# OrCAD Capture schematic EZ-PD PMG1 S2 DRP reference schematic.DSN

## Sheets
1 02. PMG1-S2 CONTROLLER: size A3; title: PMG1-S2 DRP REFERENCE DESIGN; rev: 01; note: 630-XXXXX-XX
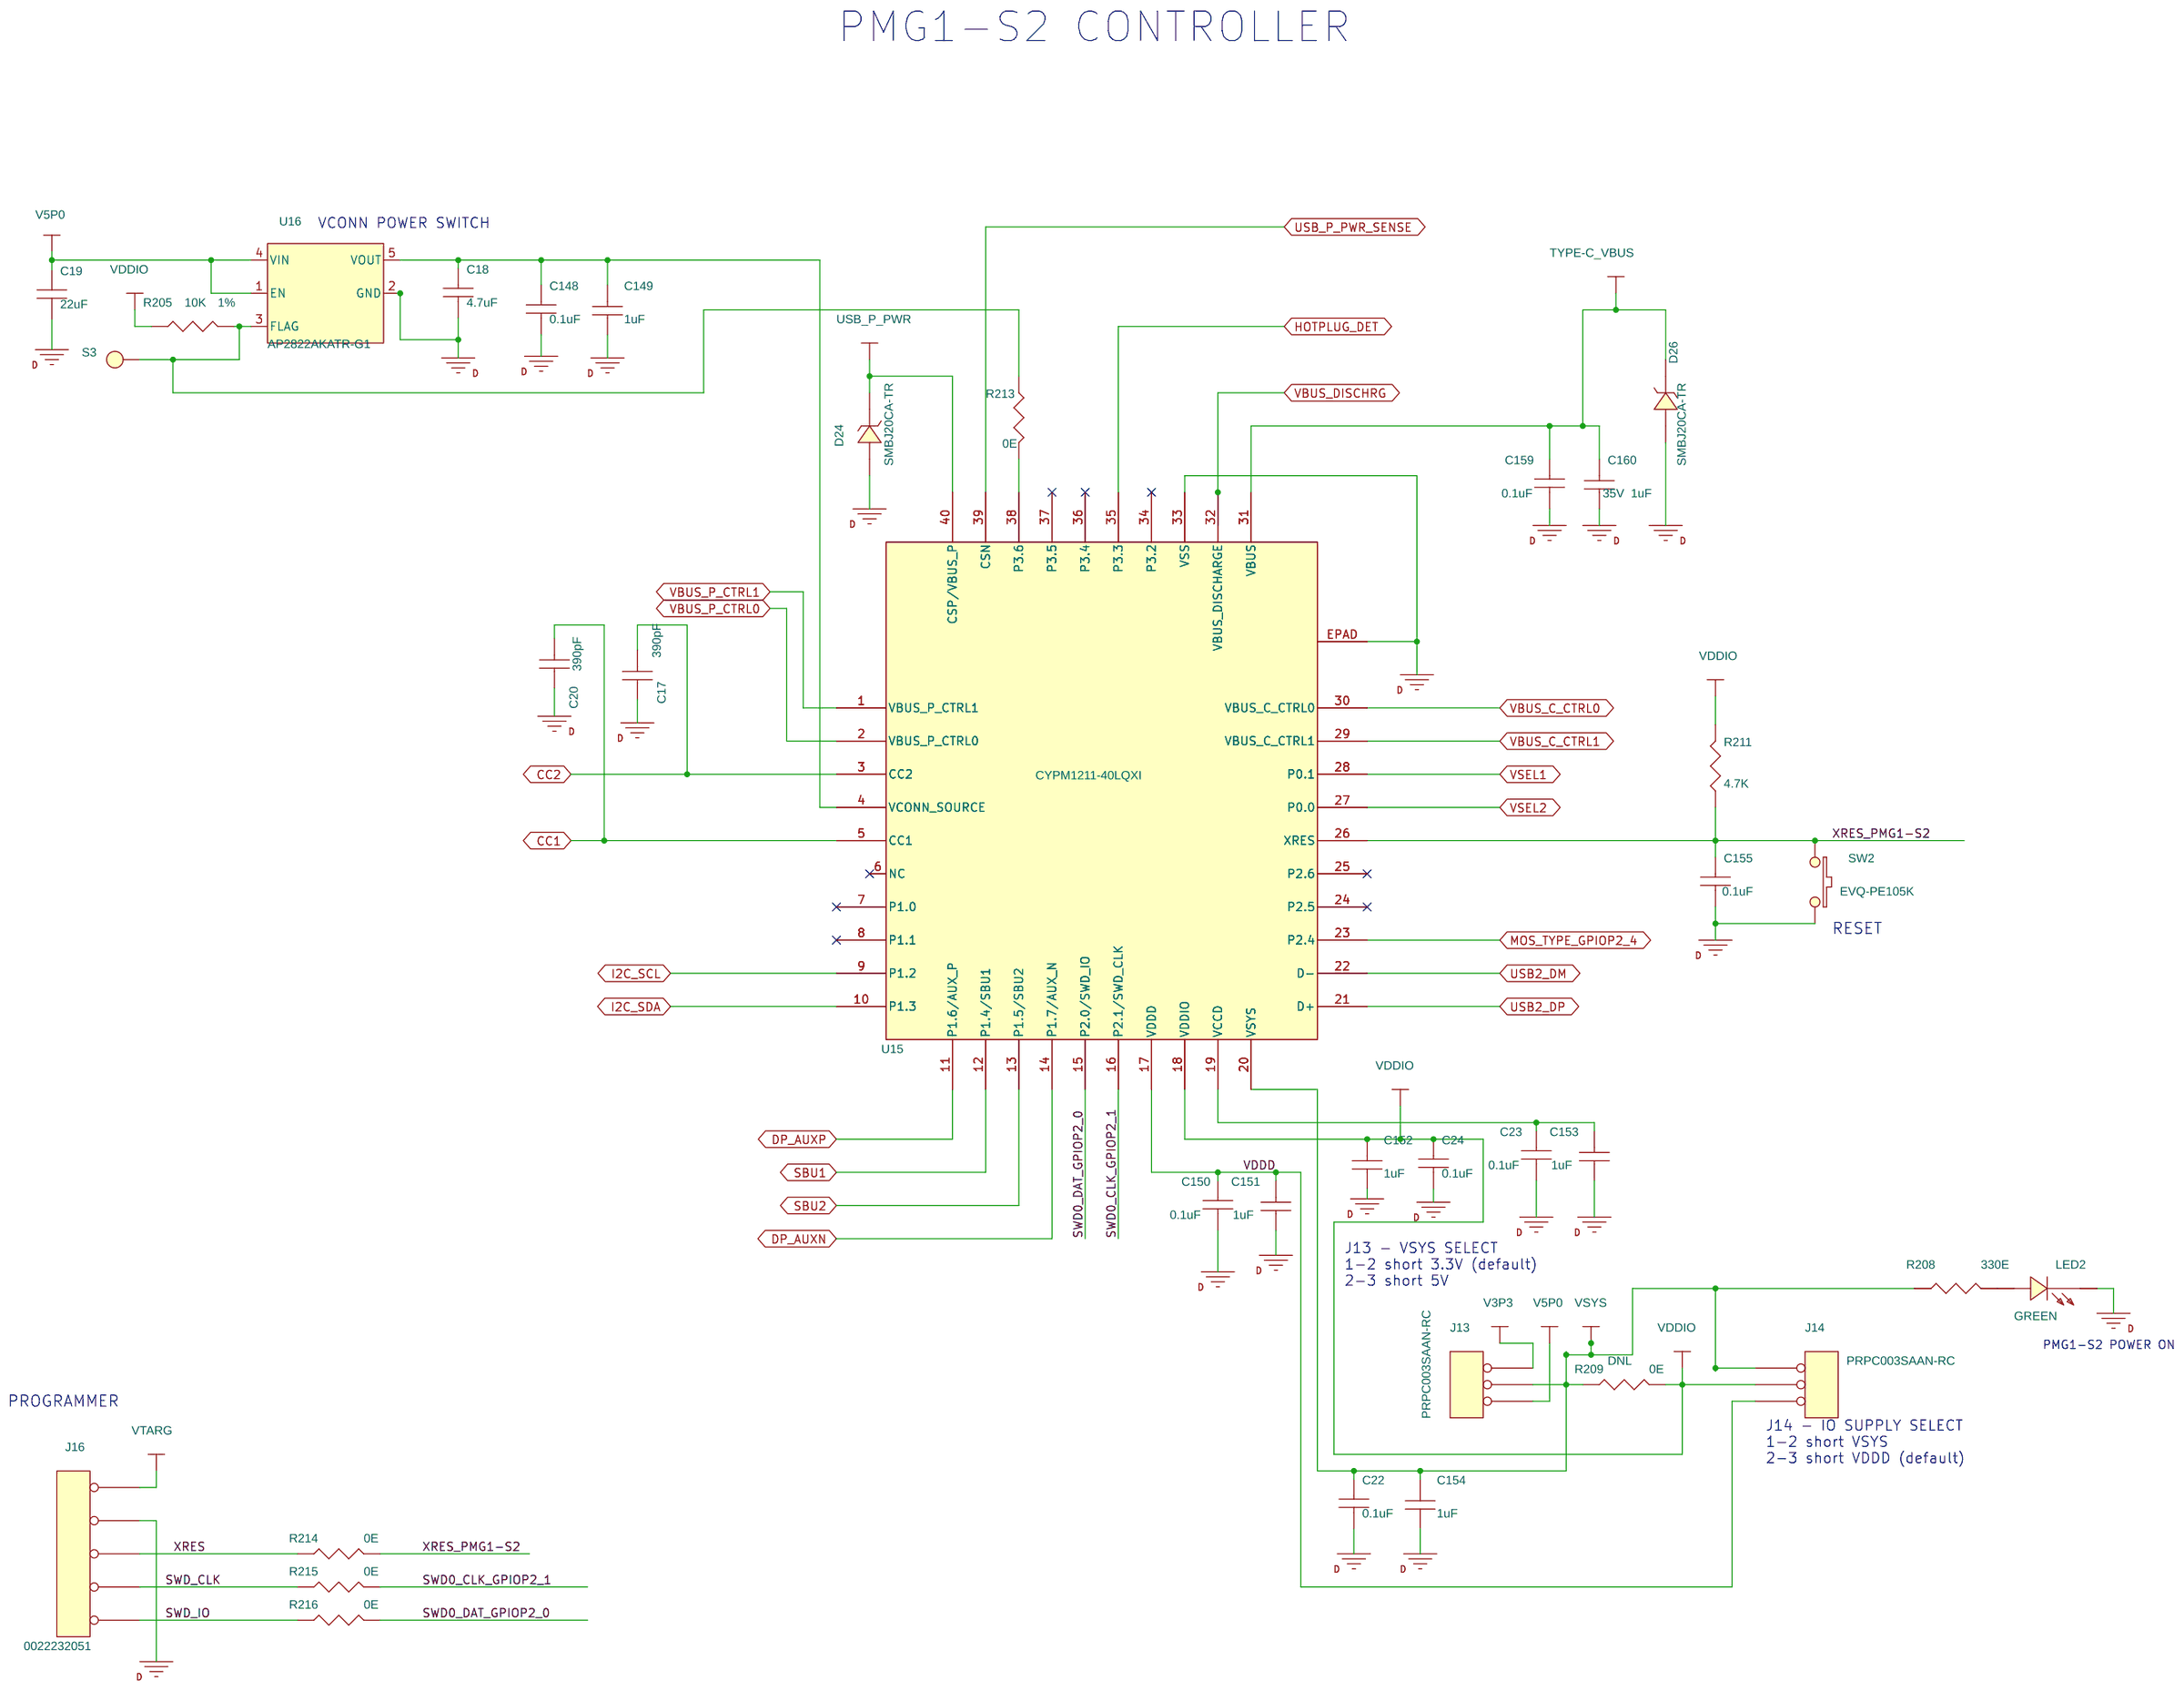
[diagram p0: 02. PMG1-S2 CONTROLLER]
2 06. USB SUPERSPEED AND DISPLAY: size A3
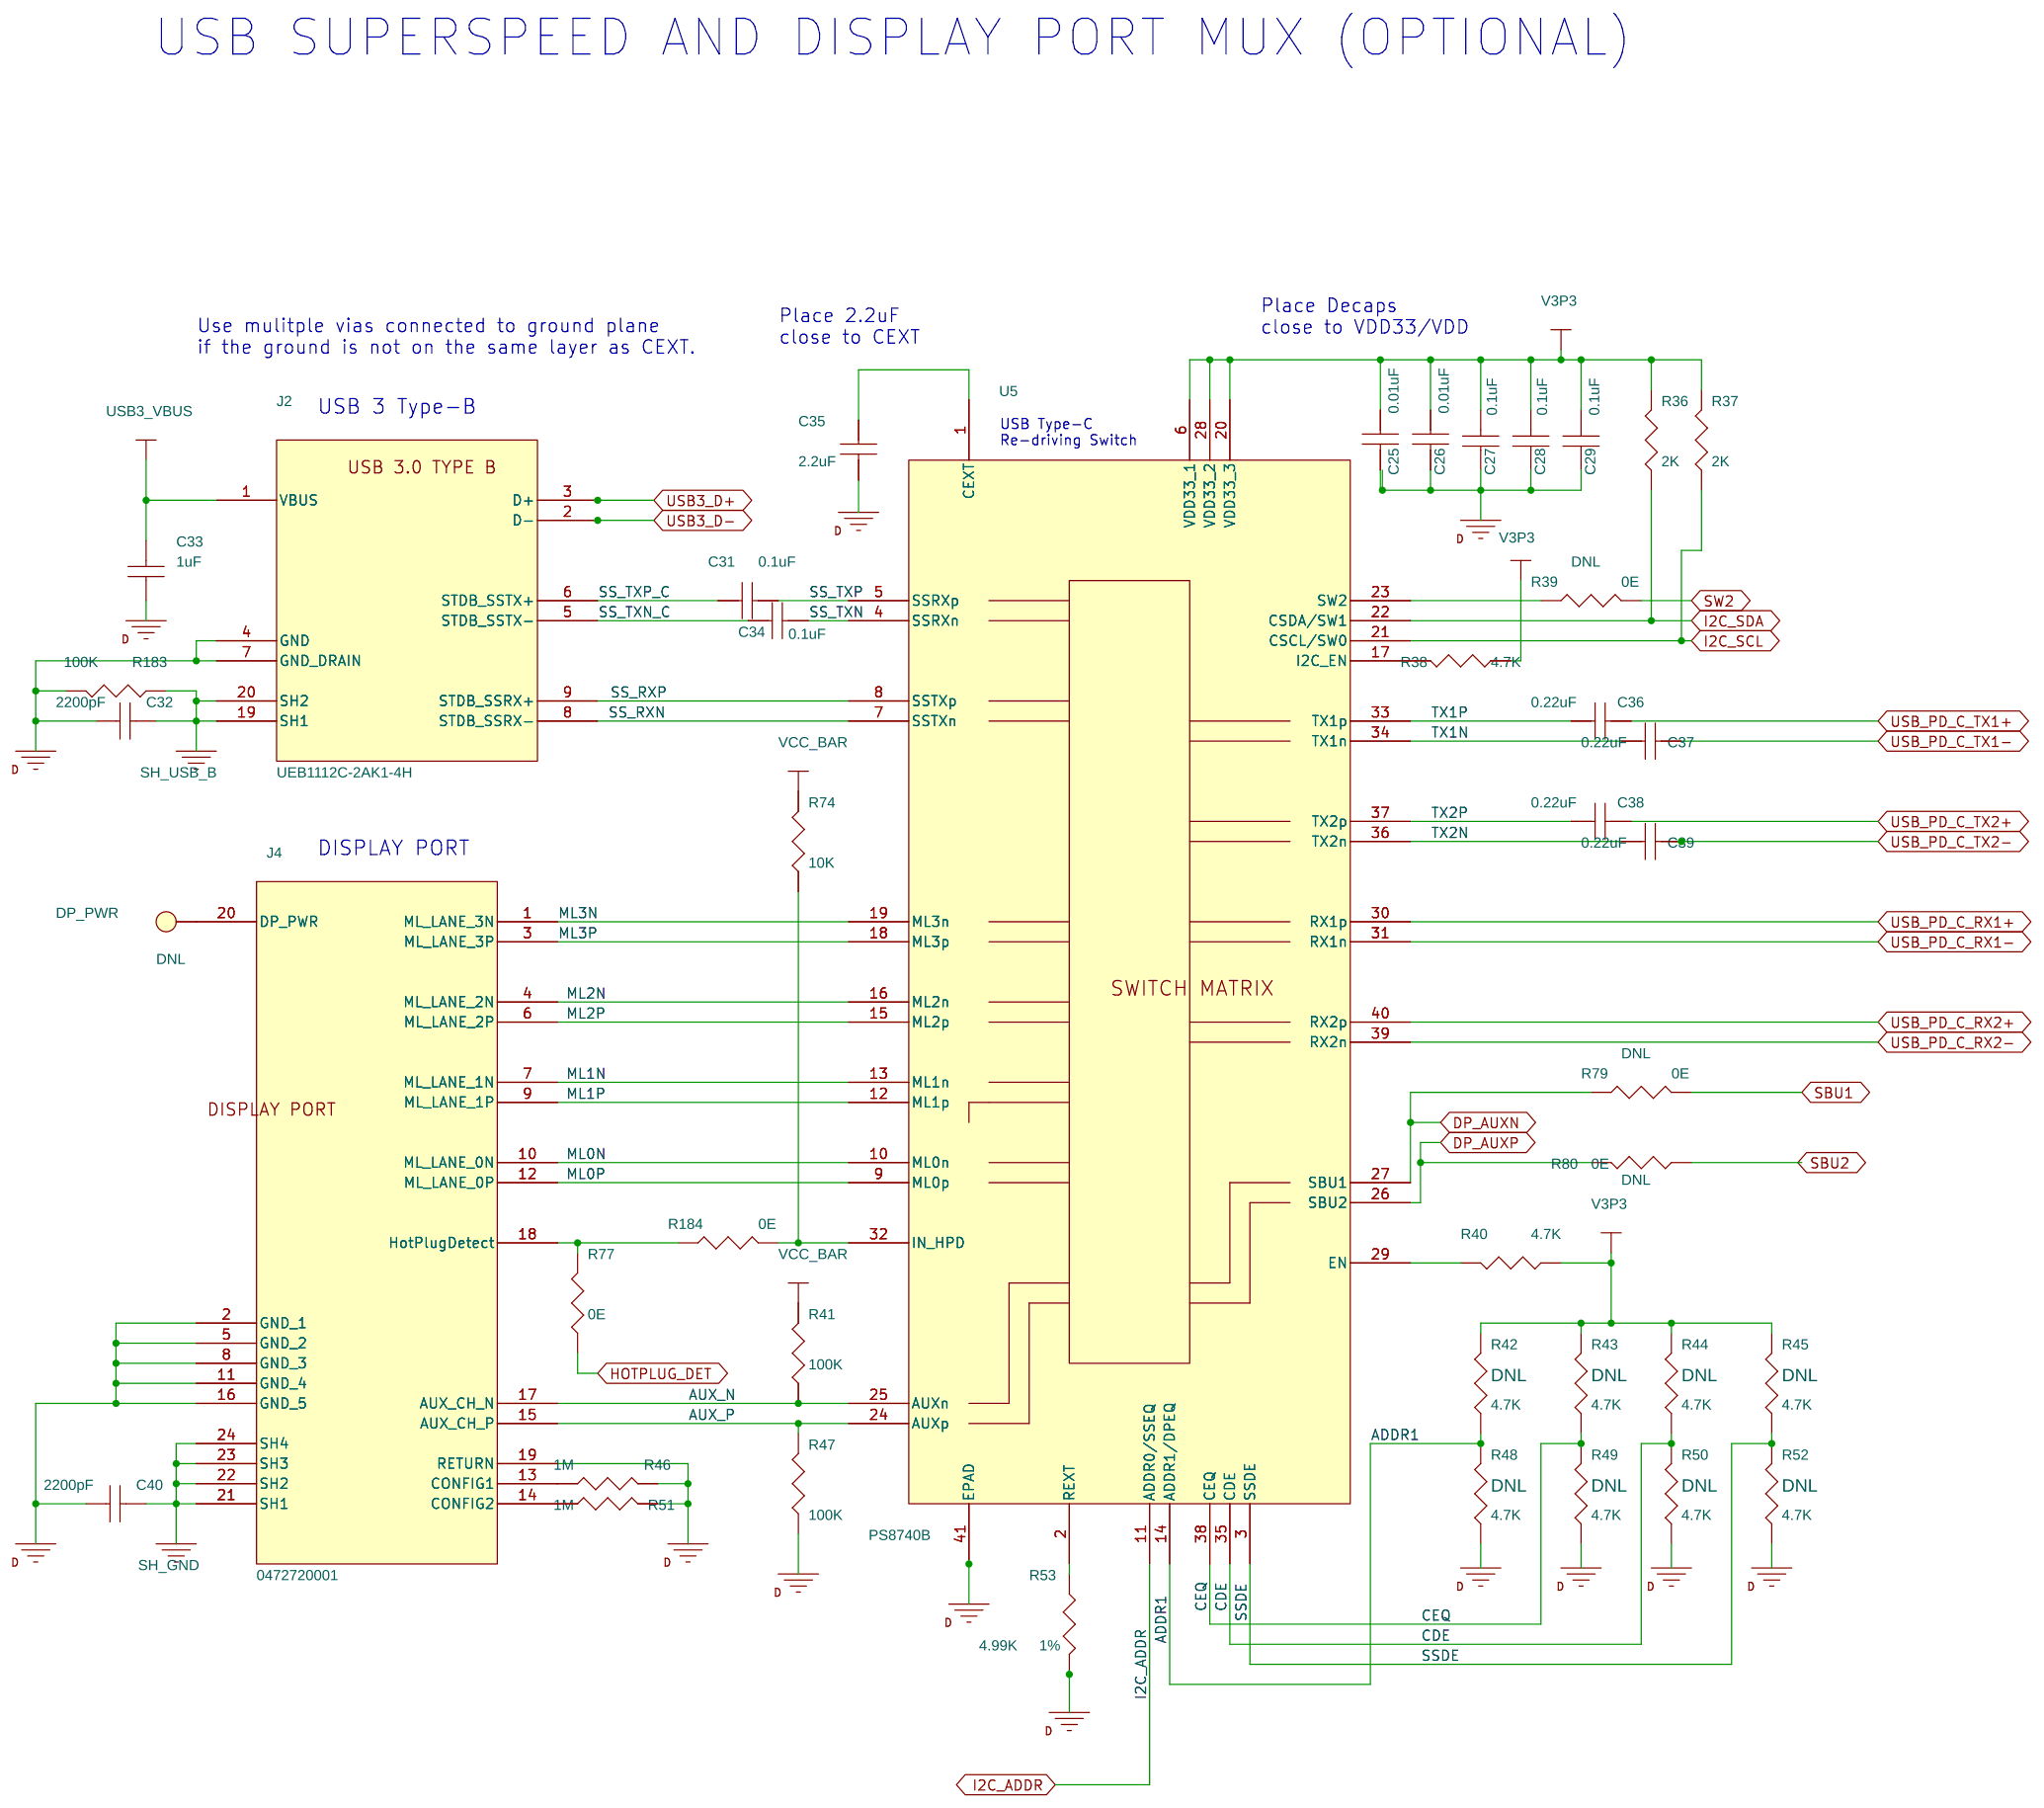
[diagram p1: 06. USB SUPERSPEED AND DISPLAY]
3 03. STEP DOWN REGULATORS: size A4
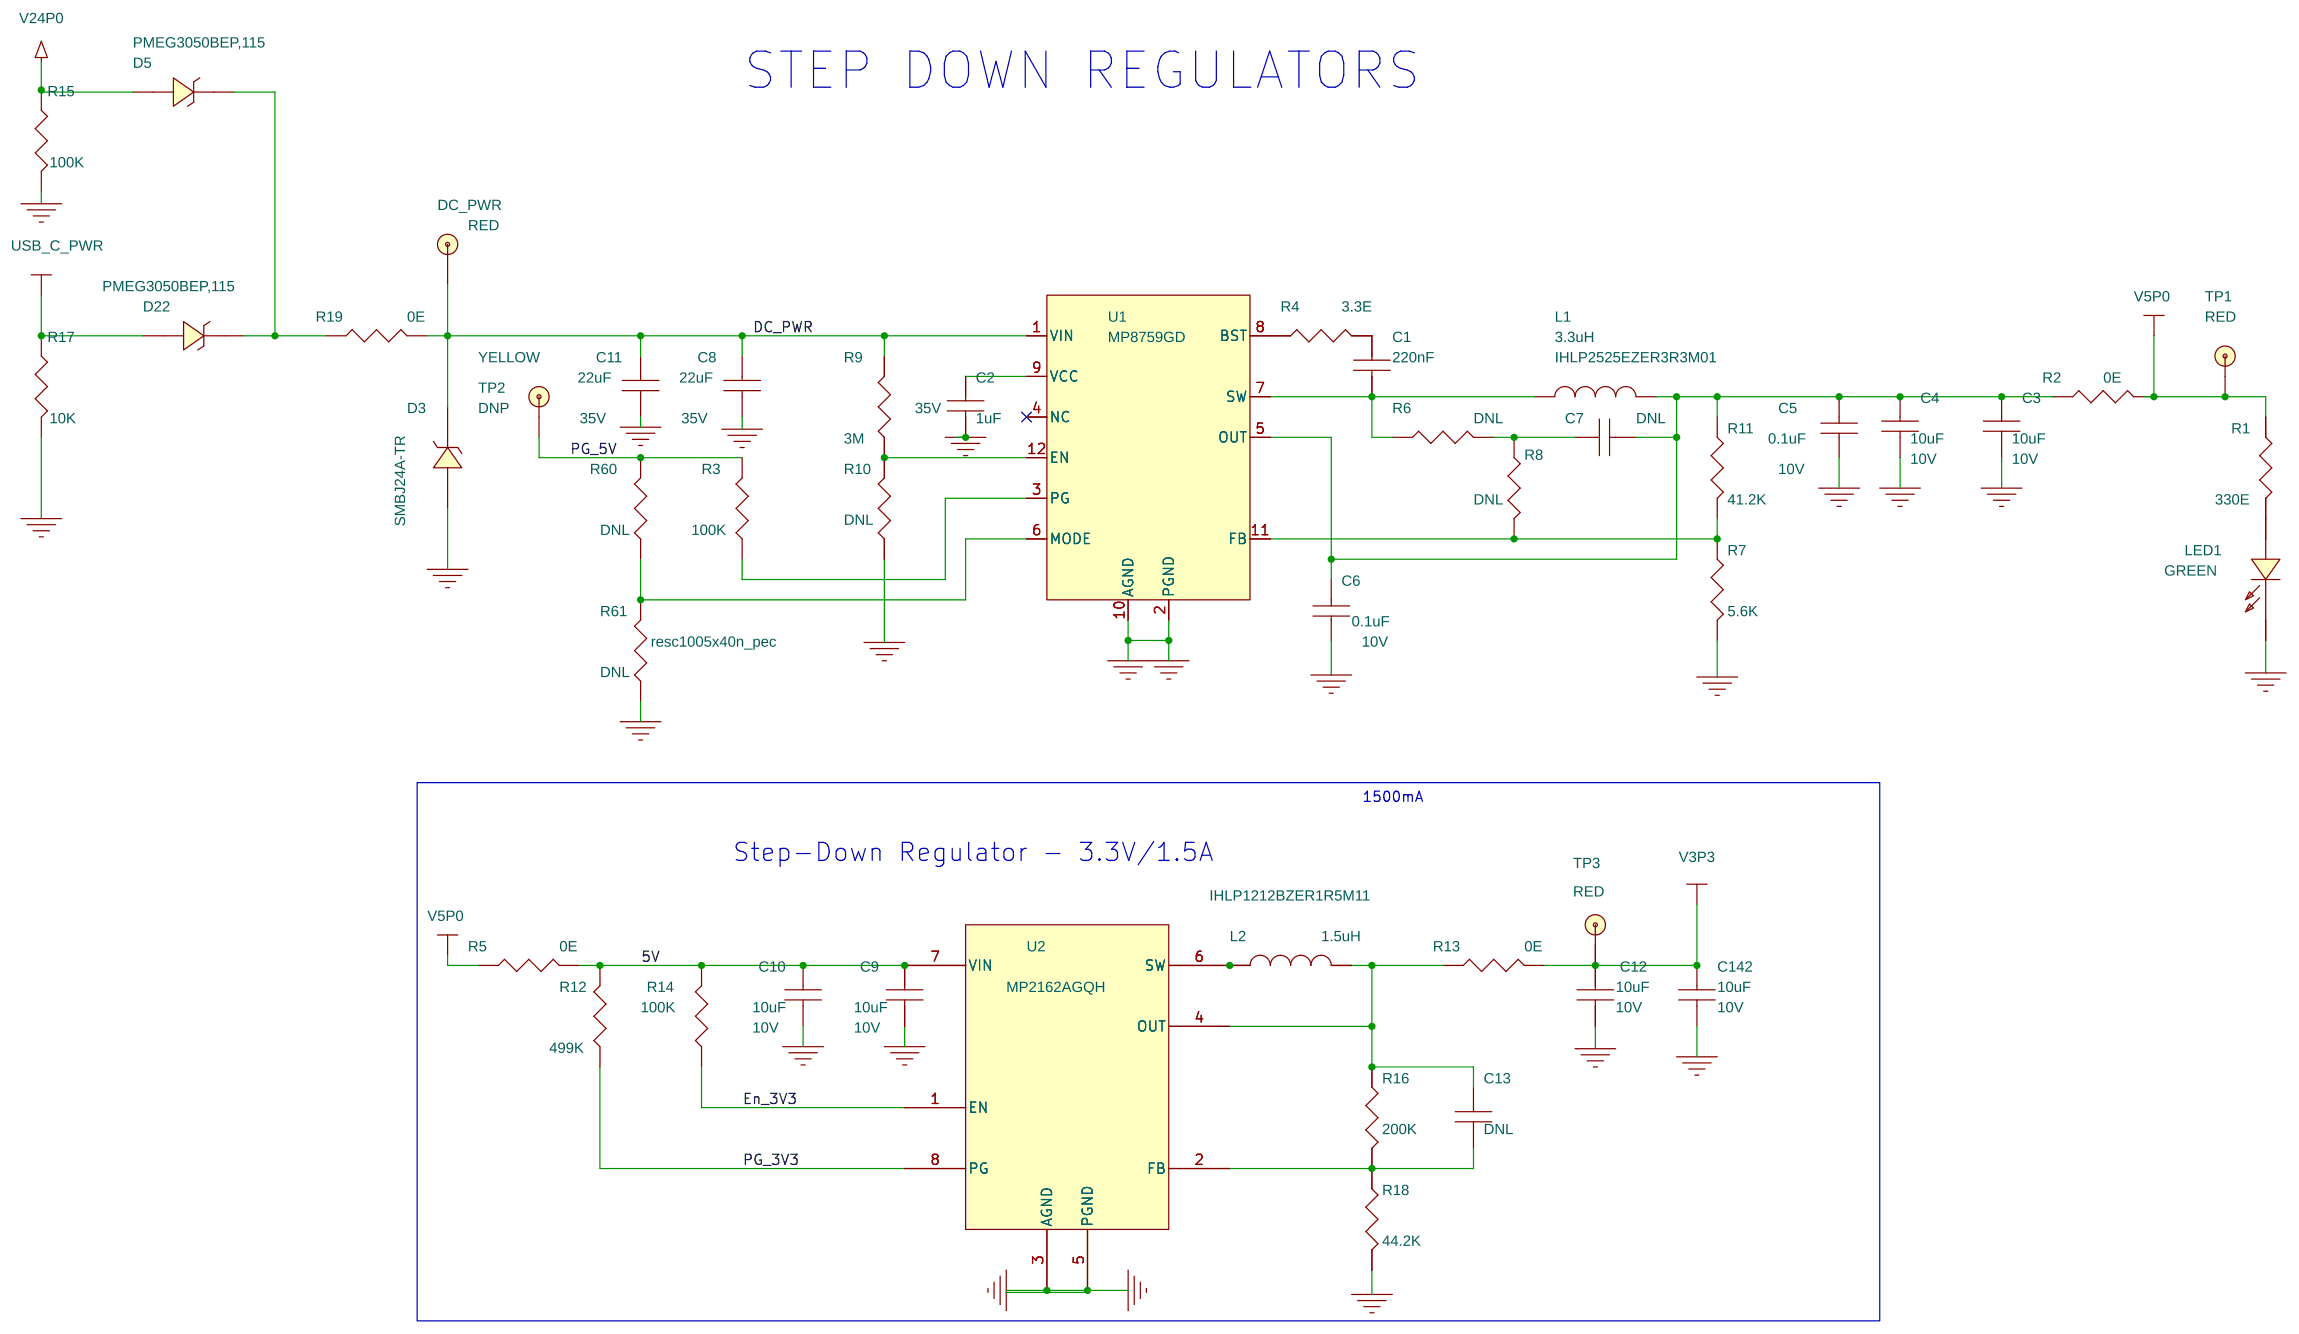
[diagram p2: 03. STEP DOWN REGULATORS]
4 04. PD REGULATOR: size A3
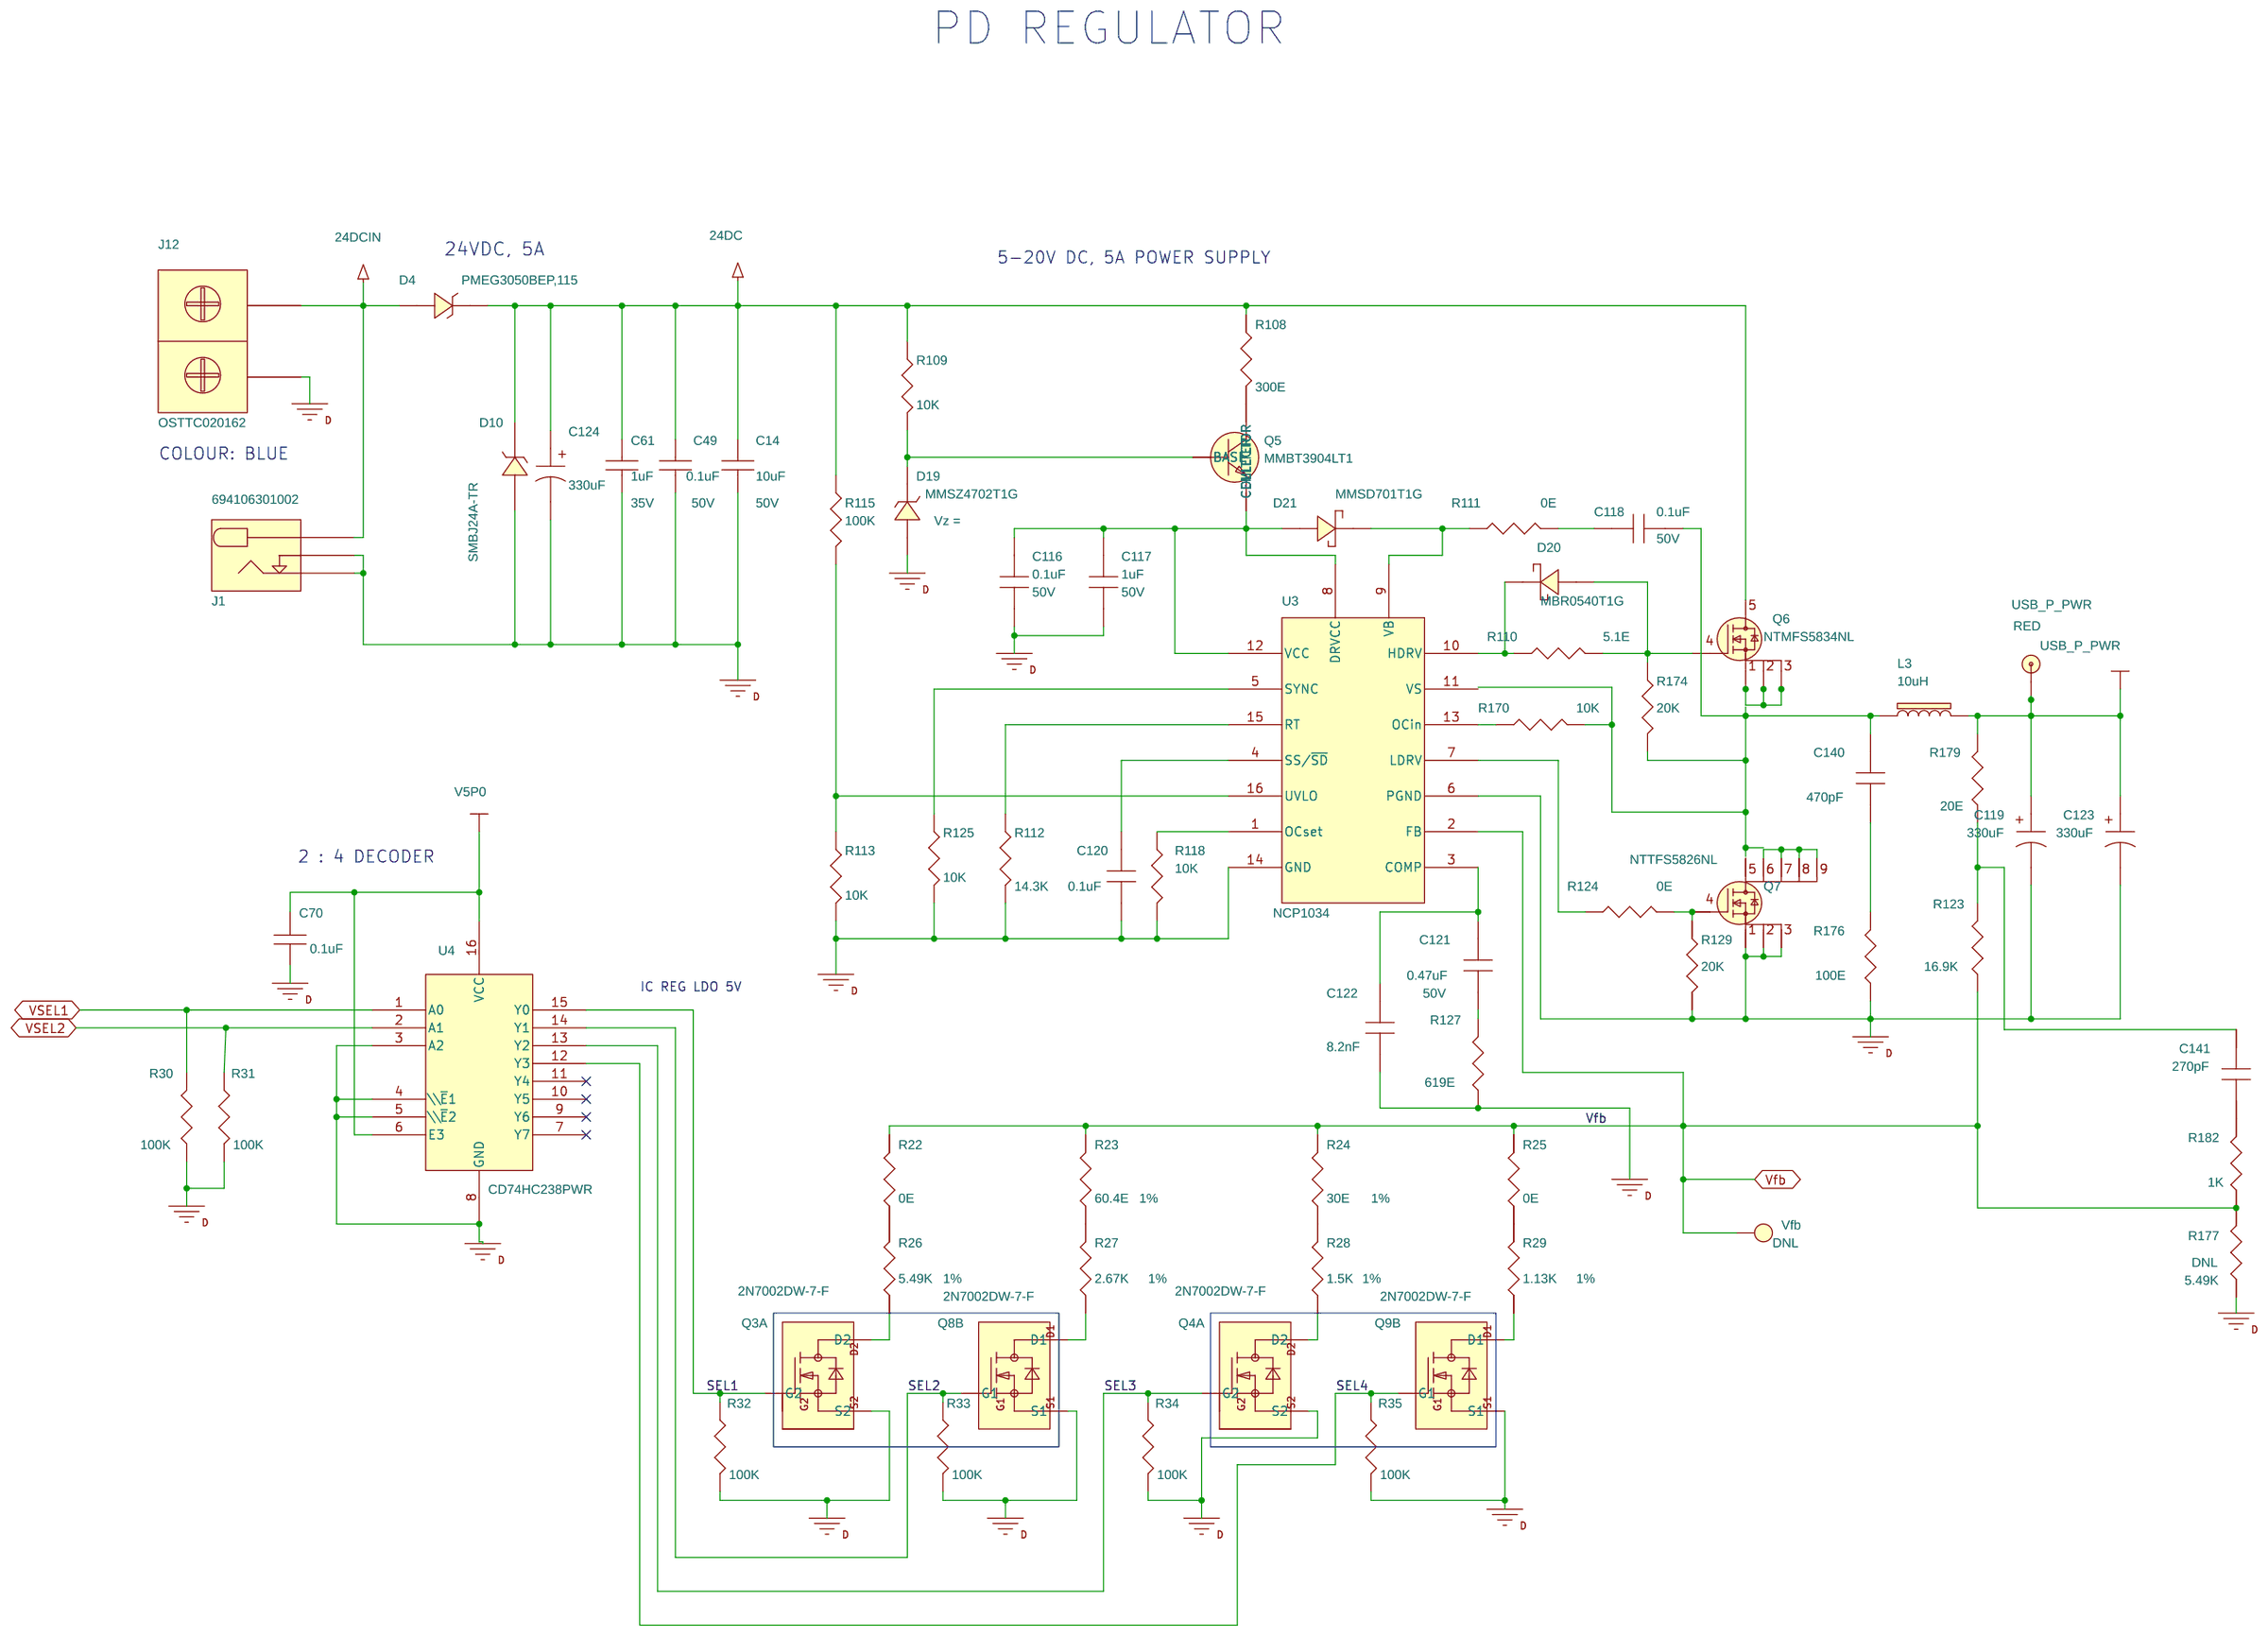
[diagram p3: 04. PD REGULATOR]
5 01.TITLE PAGE
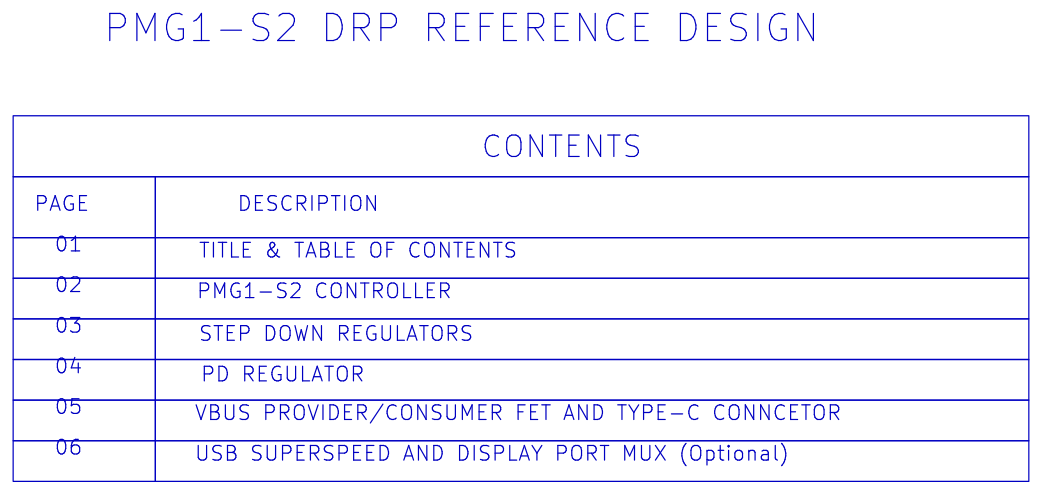
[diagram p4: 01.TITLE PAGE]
6 05. VBUS PROVIDER/CONSUMER FET: size A3
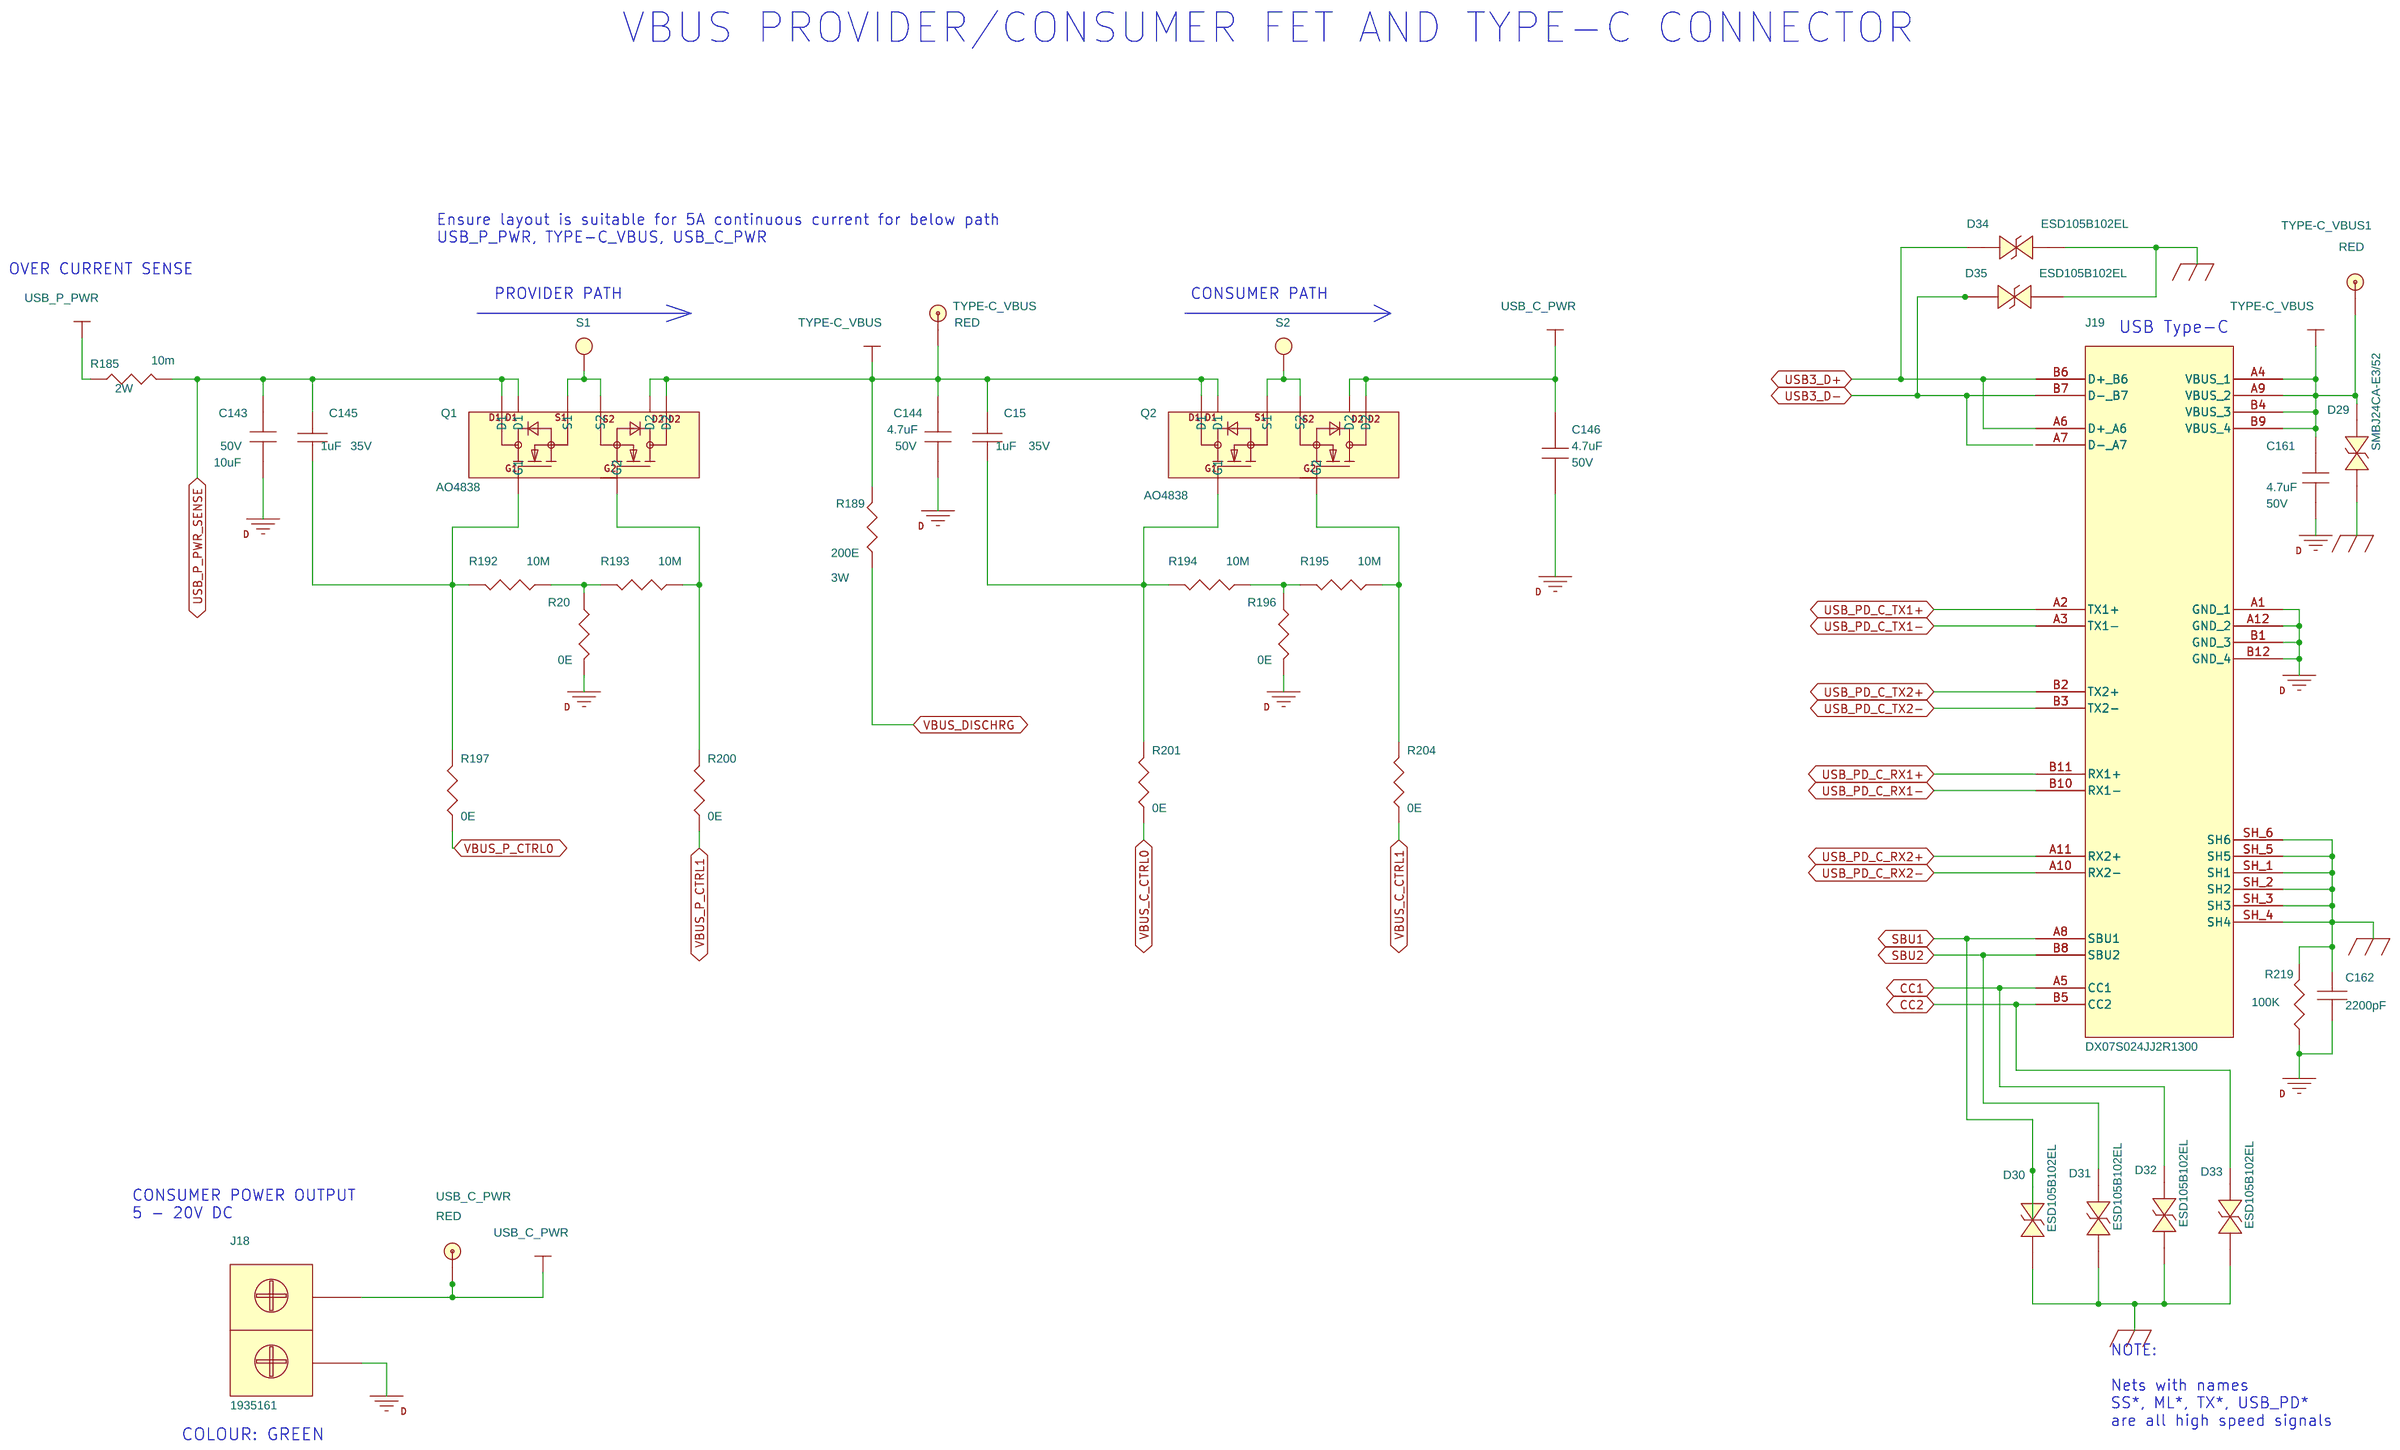
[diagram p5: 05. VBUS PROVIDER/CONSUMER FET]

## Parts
sheet 02. PMG1-S2 CONTROLLER
C17  390pF  [capc1005x56n_cyps]
C18  4.7uF  [capc1005x56n_cyps]
C19  22uF  [capc1005x56n_cyps]
C20  390pF  [capc1005x56n_cyps]
C22  0.1uF  [capc1005x56n_cyps]
C23  0.1uF  [capc1005x56n_cyps]
C24  0.1uF  [capc1005x56n_cyps]
C148  0.1uF  [capc1005x56n_cyps]
C149  1uF  [capc1005x56n_cyps]
C150  0.1uF  [capc1005x56n_cyps]
C151  1uF  [capc1005x56n_cyps]
C152  1uF  [capc1005x56n_cyps]
C153  1uF  [capc1005x56n_cyps]
C154  1uF  [capc1005x56n_cyps]
C155  0.1uF  [capc1005x56n_cyps]
C159  0.1uF  [capc1005x56n_cyps]
C160  1uF  [capc1005x56n_cyps]
D24  SMBJ20CA-TR  [SMBJ24A-TR]
D26  SMBJ20CA-TR  [SMBJ24A-TR]
J13  PRPC003SAAN-RC  [hdr3x1]
J14  PRPC003SAAN-RC  [hdr3x1]
J16  0022232051  [hdr5_keyed_m]
LED2  GREEN  [ledc1608x80n]
R205  10K  [resc1005x40n_pec]
R208  330E  [resc1608x55n_pec]
R209  0E  [resc1005x40n_pec]
R211  4.7K  [resc1005x40n_pec]
R213  0E  [resc1005x40n_pec]
R214  0E  [resc1005x40n_pec]
R215  0E  [resc1005x40n_pec]
R216  0E  [resc1005x40n_pec]
S3  T POINT R  [sip1aa]
SW2  EVQ-PE105K  [switch-evq-pe105k_5mm]
U15  CYPM1211-40LQXI  [QFN50P600X600X60-41M]
U16  AP2822AKATR-G1  [SOT95P280X145-5L30N]
sheet 03. STEP DOWN REGULATORS
C1  220nF  [capc1005x56n_cyps]
C2  1uF  [capc1608x90n_ty]
C3  10uF  [CAPC1608X90N_TY]
C4  10uF  [CAPC1608X90N_TY]
C5  0.1uF  [capc1005x56n_cyps]
C6  0.1uF  [capc1005x56n_cyps]
C7  DNP  [capc1005x56n_cyps]
C8  22uF  [WSL1206]
C9  10uF  [CAPC1608X90N_TY]
C10  10uF  [CAPC1608X90N_TY]
C11  22uF  [WSL1206]
C12  10uF  [CAPC1608X90N_TY]
C13  DNL  [capc1005x56n_cyps]
C142  10uF  [CAPC1608X90N_TY]
D3  SMBJ24A-TR  [SMBJ24A-TR]
D5  PMEG3050BEP,115  [SOD128]
D22  PMEG3050BEP,115  [SOD128]
DC_PWR  RED  [TP-43R_S]
L1  3.3uH  [IHLP2525EZER3R3M01]
L2  1.5uH  [IHLP1212AEER1R5M11]
LED1  GREEN  [ledc1608x80n]
R1  330E  [resc1608x55n_pec]
R2  0E  [RESC2012X70N_PEC]
R3  100K  [resc1005x40n_pec]
R4  3.3E  [RESC1005X40N_PEC]
R5  0E  [RESC2012X70N_PEC]
R6  DNP  [RESC1005X40N_PEC]
R7  5.6K  [RESC1005X40N_PEC]
R8  DNP  [RESC1005X40N_PEC]
R9  3M  [resc1005x40n_pec]
R10  R  [RESC1005X40N_PEC]
R11  41.2K  [RESC1005X40N_PEC]
R12  499K  [RESC1005X40N_PEC]
R13  0E  [RESC2012X70N_PEC]
R14  100K  [resc1005x40n_pec]
R15  100K  [resc1005x40n_pec]
R16  200K  [RESC1005X40N_PEC]
R17  10K  [resc1005x40n_pec]
R18  44.2K  [RESC1005X40N_PEC]
R19  0E  [RESC2012X70N_PEC]
R60  DNL  [resc1005x40n_pec]
R61  DNL  [resc1005x40n_pec]
TP1  RED  [TP-43R_S]
TP2  YELLOW  [TP-43R_S]
TP3  RED  [TP-43R_S]
U1  MP8759GD  [QFN12_2X3mm]
U2  MP2162AGQH  [QFN8_2P0X1P5]
sheet 04. PD REGULATOR
C14  10uF  [capc3225x280n_tdk]
C49  0.1uF  [capc1608x90n_ty]
C61  1uF  [capc1608x90n_ty]
C70  0.1uF  [capc1005x56n_cyps]
C116  0.1uF  [capc1005x56n_cyps]
C117  1uF  [capc1608x90n_ty]
C118  0.1uF  [capc1005x56n_cyps]
C119  330uF  [CAPAE1030X1050D1200DD460L350N]
C120  0.1uF  [capc1608x90n_ty]
C121  0.47uF  [capc1608x90n_ty]
C122  8.2nF  [capc1005x56n_cyps]
C123  330uF  [CAPAE1030X1050D1200DD460L350N]
C124  330uF  [CAPAE1030X1050D1200DD460L350N]
C140  470pF  [capc1608x90n_ty]
C141  270pF  [capc1005x56n_cyps]
D4  PMEG3050BEP,115  [PMEG3050EP-115]
D10  SMBJ24A-TR  [SMBJ24A-TR]
D19  MMSZ4702T1G  [SOD123_MMSZ4702T1G]
D20  MBR0540T1G  [SOD-123_MBR0540T1G]
D21  MMSD701T1G  [SOD-123_MMSD701T1G]
J1  694106301002  [RAPC712]
J12  OSTTC020162  [TERMINAL_BLOCK_2PIN]
L3  10uH  [ind_SRP1245A]
Q3  2N7002DW-7-F  [SOT65P210X110-6L15N]  (section A)
Q4  2N7002DW-7-F  [SOT65P210X110-6L15N]  (section A)
Q5  MMBT3904LT1  [SOT23_MMBT3904LT1]
Q6  NTMFS5834NL  [SO-8FL_NTMFS5834NLT1G]
Q7  NTTFS5826NL  [WDFN8_NTTFS5826NLTAG]
Q8  2N7002DW-7-F  [SOT65P210X110-6L15N]  (section B)
Q9  2N7002DW-7-F  [SOT65P210X110-6L15N]  (section B)
R22  0E  [resc1005x40n_pec]
R23  60.4E  [resc1005x40n_pec]
R24  30E  [resc1005x40n_pec]
R25  0E  [resc1005x40n_pec]
R26  5.49K  [resc1005x40n_pec]
R27  2.67K  [resc1005x40n_pec]
R28  1.5K  [resc1005x40n_pec]
R29  1.13K  [resc1005x40n_pec]
R30  100K  [resc1005x40n_pec]
R31  100K  [resc1005x40n_pec]
R32  100K  [resc1005x40n_pec]
R33  100K  [resc1005x40n_pec]
R34  100K  [resc1005x40n_pec]
R35  100K  [resc1005x40n_pec]
R108  300E  [resc1608x55n_pec]
R109  10K  [resc1608x55n_pec]
R110  5.1E  [resc1608x55n_pec]
R111  0E  [resc1608x55n_pec]
R112  14.3K  [resc1608x55n_pec]
R113  10K  [resc1608x55n_pec]
R115  100K  [resc1608x55n_pec]
R118  10K  [resc1608x55n_pec]
R123  16.9K  [resc1608x55n_pec]
R124  0E  [resc1608x55n_pec]
R125  10K  [resc1608x55n_pec]
R127  619E  [resc1608x55n_pec]
R129  20K  [resc1608x55n_pec]
R170  10K  [resc1608x55n_pec]
R174  20K  [resc1608x55n_pec]
R176  100E  [resc1608x55n_pec]
R177  5.49K  [resc1608x55n_pec]
R179  20E  [resc1608x55n_pec]
R182  1K  [resc1608x55n_pec]
U3  NCP1034  [TO-92_NCP1034DR2G]
U4  CD74HC238PWR  [SOP65P640X120-16L25N]
USB_P_PWR  RED  [TP-43R_S]
Vfb  RED  [TP-43R_S]
sheet 05. VBUS PROVIDER/CONSUMER FET
C15  1uF  [capc1005x56n_cyps]
C143  10uF  [capc3225x280n_tdk]
C144  4.7uF  [capc3225x280n_tdk]
C145  1uF  [capc1005x56n_cyps]
C146  4.7uF  [capc3225x280n_tdk]
C161  4.7uF  [capc3225x280n_tdk]
C162  2200pF  [C1808]
D29  SMBJ24CA-E3/52  [SMBJ24CA_3P679_2H44]
D30  ESD105B102EL  [ESD_TSLP2_0P65_0H4]
D31  ESD105B102EL  [ESD_TSLP2_0P65_0H4]
D32  ESD105B102EL  [ESD_TSLP2_0P65_0H4]
D33  ESD105B102EL  [ESD_TSLP2_0P65_0H4]
D34  ESD105B102EL  [ESD_TSLP2_0P65_0H4]
D35  ESD105B102EL  [ESD_TSLP2_0P65_0H4]
J18  1935161  [1935161]
J19  DX07S024JJ2R1300  [USB-PD_TYPE-C]
Q1  AO4838  [SOIC127P600X175-8L20N]
Q2  AO4838  [SOIC127P600X175-8L20N]
R20  0E  [resc1005x40n_pec]
R185  10m  [RESC6432X67N]
R189  200E  [RESC6331X84N]
R192  10M  [resc1005x40n_pec]
R193  10M  [resc1005x40n_pec]
R194  10M  [resc1005x40n_pec]
R195  10M  [resc1005x40n_pec]
R196  0E  [resc1005x40n_pec]
R197  0E  [resc1005x40n_pec]
R200  0E  [resc1005x40n_pec]
R201  0E  [resc1005x40n_pec]
R204  0E  [resc1005x40n_pec]
R219  100K  [resc1005x40n_pec]
S1  T POINT R  [sip1aa]
S2  T POINT R  [sip1aa]
TYPE-C_VBUS  RED  [TP-43R_S]
TYPE-C_VBUS1  RED  [TP-43R_S]
USB_C_PWR  RED  [TP-43R_S]
sheet 06. USB SUPERSPEED AND DISPLAY
C25  0.01uF  [capc1005x56n_cyps]
C26  0.01uF  [capc1005x56n_cyps]
C27  0.1uF  [capc1005x56n_cyps]
C28  0.1uF  [capc1005x56n_cyps]
C29  0.1uF  [capc1005x56n_cyps]
C31  0.1uF  [capc1005x56n_cyps]
C32  2200pF  [C1808]
C33  1uF  [capc1005x56n_cyps]
C34  0.1uF  [capc1005x56n_cyps]
C35  2.2uF  [capc1608x90n_ty]
C36  0.22uF  [capc1005x56n_cyps]
C37  0.22uF  [capc1005x56n_cyps]
C38  0.22uF  [capc1005x56n_cyps]
C39  0.22uF  [capc1005x56n_cyps]
C40  2200pF  [C1808]
DP_PWR  RED  [TP-43R_S]
J2  UEB1112C-2AK1-4H  [USB_CONN_GSB3211311WEU]
J4  0472720001  [CONN20_0472720001]
R36  2K  [resc1005x40n_pec]
R37  2K  [resc1005x40n_pec]
R38  4.7K  [resc1005x40n_pec]
R39  0E  [resc1005x40n_pec]
R40  4.7K  [resc1005x40n_pec]
R41  100K  [resc1005x40n_pec]
R42  4.7K  [resc1005x40n_pec]
R43  4.7K  [resc1005x40n_pec]
R44  4.7K  [resc1005x40n_pec]
R45  4.7K  [resc1005x40n_pec]
R46  1M  [resc1608x55n_pec]
R47  100K  [resc1005x40n_pec]
R48  4.7K  [resc1005x40n_pec]
R49  4.7K  [resc1005x40n_pec]
R50  4.7K  [resc1005x40n_pec]
R51  1M  [resc1608x55n_pec]
R52  4.7K  [resc1005x40n_pec]
R53  4.99K  [resc1005x40n_pec]
R74  10K  [resc1005x40n_pec]
R77  0E  [resc1005x40n_pec]
R79  0E  [resc1005x40n_pec]
R80  0E  [resc1005x40n_pec]
R183  100K  [resc1005x40n_pec]
R184  0E  [resc1005x40n_pec]
U5  PS8740B  [QFN40P600X400X80-41T260X460N]

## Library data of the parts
C17 C20 = CAP_NP: CAP CER 390pF 50V X7R 0402; DIGI-KEY PART NO: 490-3249-1-ND; MFG Part number: GRM155R71H391KA01D; Manufacturer: Murata Electronics North America; Price: 0.1; VOLTAGE: 50V
C18 = CAP_NP: CAP CER 4.7UF 10V 20% X5R 0402; DIGI-KEY PART NO: 445-8023-1-ND; MFG Part number: C1005X5R1A475M050BC; Manufacturer: TDK Corporation; Price: 0.33; TOLERANCE: 20%; Voltage: 10V
C19 = CAP_NP: CAP CER 22µF 6.3V 20% X5R 0402; DIGI-KEY PART NO: 1276-6834-1-ND; MFG Part number: CL05A226MQ5QUNC; Manufacturer: Samsung Electro-Mechanics America Inc.; Price: 0.87; TOLERANCE: 20%; Voltage: 6.3V
C22-C24 C148 C150 C159 = CAP_NP: CAP CER 0.1UF 50V X7R 0402; DIGI-KEY PART NO: 445-5932-1-ND; MFG Part number: C1005X7R1H104K050BB; Manufacturer: TDK Corporation; Price: 0.15; Voltage: 50V
C149 C151-C154 = CAP_NP: CAP CER 1UF 10V X5R 0402; DIGI-KEY PART NO: 490-3890-1-ND; MFG Part number: GRM155R61A105KE15D; Manufacturer: Murata Electronics North America; Price: 0.1; Voltage: 10V
C155 = CAP_NP: CAP CER 0.1UF 10V 10% X7R 0402; DIGI-KEY PART NO: 445-4958-1-ND; MFG Part number: C1005X7R1A104K050BB; Manufacturer: TDK Corporation; Price: 0.1; Voltage: 50V
C15 C145 C160 = CAP_NP: CAP CER 1UF 35V X5R 0402; DIGI-KEY PART NO: 445-9073-1-ND; MFG Part number: C1005X5R1V105K050BC; Manufacturer: TDK Corporation; Price: 0.18; Voltage: 35V
D24 D26 = BZX84C18_SOT_0: TVS DIODE 20VWM 42.8VC SMB; DIGI-KEY PART NO: 497-6513-1-ND; Manufacturer: STMicroelectronics; Price: 0.44
J13 J14 = CON3_0: CONN HEADER .100" SNGL STR 3POS; DIGI-KEY PART NO: S1011EC-03-ND; Manufacturer: Sullins Connector Solutions; Price: 0.18
J16 = CON5_0: CONN HEADER 5POS .100 VERT TIN; DIGI-KEY PART NO: WM4203-ND; MFG Part number: 22232051; Manufacturer: Molex, LLC; Price: 0.35
LED1 LED2 = LED_GREEN2_0: LED GREEN CLEAR 0603 SMD; DIGI-KEY PART NO: 160-1183-1-ND; MFG Part number: LTST-C190GKT; Manufacturer: Lite-On Inc.; Price: 0.28
R205 = RESISTOR: RES 10K OHM 1/16W 1% 0402; DIGI-KEY PART NO: 1276-3431-1-ND; MFG Part number: RC1005F103CS; Manufacturer: Samsung Electro-Mechanics America Inc.; Price: 0.1; TOLERANCE: 1%
R208 = RESD,0402,5%,1_32W,10K: RES SMD 330 OHM 5% 1/10W 0603; DIGI-KEY PART NO: 311-330GRCT-ND; MFG Part number: RC0603JR-07330RL; Manufacturer: Yageo; Price: 0.1; Tolerance: 5%
R39 R79 R80 R209 = R: RES 0.0 OHM 1/16W JUMP 0402 SMD; DIGI-KEY PART NO: 541-0.0JCT-ND; DNL: DNL; MFG Part number: CRCW04020000Z0ED; Manufacturer: Vishay Dale; Price: 0.074
R211 = RESISTOR: RES SMD 4.7K OHM 5% 1/16W 0402; DIGI-KEY PART NO: 311-4.7KJRCT-ND; MFG Part number: RC0402JR-074K7L; Manufacturer: Yageo; Price: 0.1; TOLERANCE: 5%
R20 R22 R25 R77 R184 R196 R197 R200 R201 R204 R213-R216 = R: RES 0.0 OHM 1/16W JUMP 0402 SMD; DIGI-KEY PART NO: 541-0.0JCT-ND; MFG Part number: CRCW04020000Z0ED; Manufacturer: Vishay Dale; Price: 0.074
S1-S3 = T_POINT_R
SW2 = SW_PB_SPST: SWITCH TACTILE SPST-NO 0.05A 12V; DIGI-KEY PART NO: P13594SCT-ND; Manufacturer: Panasonic Electronic Components; Price: 0.72
U15 = CYPM1211-40LQXI_5: Power Delivery Microcontroller; Manufacturer: Cypress Semiconductor; Mfr_Name: Cypress Semiconductor
U16 = AP2822AKATR-G1_1: IC USB POWER SWITCH SOT25; DIGI-KEY PART NO: AP2822AKATR-G1DICT-ND; Manufacturer: Diodes Incorporated; Price: 0.47
C1 = C_np: CAP CER 0.22UF 25V X5R 0402; MFG Part number: C1005X5R1E224K050BC; Manufacturer: TDK CORPORATION; Part No.: C1005X5R1E224K050BC
C2 C61 = CAP_NP: CAP CER 1UF 35V X7R 0603; DIGI-KEY PART NO: 445-7414-1-ND; MFG Part number: C1608X7R1V105K080AC; Manufacturer: TDK Corporation; Price: 0.24; VOLTAGE: 35V
C3 C4 = C_np: CAP CER 10UF 10V 10% X5R 0603; Descriptions: CAP CER 22UF 35V X5R 0805; MANUFACTURER P/N: C2012X5R1V226M125AC; MFG Part number: C1608X5R1A106K080AC; Manufacturer: TDK CORPORATION; Part No.: C1608X5R0J226M080AC; Voltage: 10V
C5 C6 = CAP_NP: CAP CER 0.1UF 10V 10% X7R 0402; Alternate Mfr #: CL05B104KP5NNNC; Alternate Mfr Part #: CL05B104KP5NNNC; Alternate manufacturer: Samsung Electro-Mechanics; MFG Part Number: C1005X7R1A104K050BB; Manufacturer: TDK Corporation; PART_NUMBER: C1005X7R1A104K050BB; RATED_VOLTAGE: 10V; Rating: 10V; Temp_Coefficient: X7R; Tolerance: 10%; VOLTAGE: 10V
C7 = C_np: BOM_IG: NO LOAD; DNL: DNL; Part No.: C1005X5R0J105M050BB
C8 C11 = C_np: CAP CER 22UF 35V X5R 1206; Descriptions: CAP CER 22UF 35V X5R 1206; MANUFACTURER P/N: C2012X5R1V226M125AC; MFG Part number: C3216X5R1V226M160AC; Manufacturer: TDK CORPORATION; Part No.: C1608X5R0J226M080AC; Voltage: 35V
C9 C10 C12 C142 = C_np: CAP CER 10UF 10V 10% X5R 0603; MFG Part number: C1608X5R1A106K080AC; Manufacturer: TDK CORPORATION; Part No.: C1608X5R0J226M080AC; Voltage: 10V
C13 = C_np: BOM_IG: NO LOAD; Part No.: C1608X5R0J226M080AC; Voltage: 10V
D3 = BZX84C18_SOT_1_v2: TVS DIODE 24VWM 50VC DO214AA; DIGI-KEY PART NO: 497-3140-1-ND; Manufacturer: STMicroelectronics; Price: 0.42
D5 D22 = BZX84C18_SOT_1_v2: DIODE SCHOTTKY 30V 5A SOD128; ALTERNATE PART NUMBER: RBR5LAM30BTR; Alternate Manufacturer: Rohm Semiconductors.; Alternate Mfr Part #: RBR5LAM30BTR; DIGI-KEY PART NO: 568-6519-1-ND; Manufacturer: NXP Semiconductors; Price: 0.48
DC_PWR TP1 TP3 = TEST_POINT: TEST POINT PC MINI .040"D RED; CLASS: DISCRETE; MFG Part number: 5000; Manufacturer: Keystone Electronics; Mfr_Name: Keystone Electronics; Mfr_Part_Number: 5000; PART_NUMBER: 5000; Package Type: TH; Part Number: 400-00001; Section: Power Supply
L1 = INDUCTOR: FIXED IND 3.3UH 8A 20.9 MOHM SMD; Cost: .01; Manufacturer: VISHAY DALE; Tolerance: NA; Voltage: NA
L2 = INDUCTOR: FIXED IND 1.5UH 3.8A 32 mOHM SMD; Cost: .01; MFG Part number: IHLP1212BZER1R5M11; Manufacturer: VISHAY DALE; Part No.: IHLP1212BZER1R5M11; Part Number: IHLP1212BZER1R5M11; Tolerance: NA; Voltage: NA
R1 = RESD,0402,5%,1_32W,10K: RES SMD 330 OHM 5% 1/10W 0603; Alternate Manufacturer: Stackpole Electronics Inc.; Alternate Mfr Part #: RMCF0603JT330R; DIGI-KEY PART NO: 311-330GRCT-ND; MFG Part number: RC0603JR-07330RL; Manufacturer: Yageo; Price: 0.1; Tolerance: 5%
R2 R5 R13 R19 = R: RES SMD 0.0 OHM JUMPER 1/8W 0805; DIGI-KEY PART NO: 311-0.0ARCT-ND; MFG Part number: RC0805JR-070RL; Manufacturer: Yageo; Price: 0.1
R3 R14 R15 = R: RES SMD 100K OHM 5% 1/10W 0402; MFG Part number: ERJ-2GEJ104X; Manufacturer: Panasonic Electronic Components; Part No.: ERJ-2GEJ104X
R4 = R: RES SMD 3.3 OHM 1% 1/6W 0402; MFG Part number: RL0510S-3R3-F; Manufacturer: Susumu; Part No.: RL0510S-3R3-F
R6 = R: BOM_IG: NO LOAD; DNL: DNL; Part No.: ERJ-1GEF1152C
R7 = R: RES SMD 5.6K OHM 5% 1/16W 0402; MFG Part number: RC0402JR-075K6L; Manufacturer: YAGEO; Part No.: RC0402JR-075K6L
R8 R10 = R: BOM_IG: NO LOAD; DNL: DNL; Part No.: ERJ-1GEF4322C
R9 = R: RES SMD 3M OHM 1% 1/16W 0402; MFG Part number: RC1005F305CS; Manufacturer: Samsung Electro-Mechanics America, Inc
R11 = R: RES SMD 41.2K OHM 1% 1/16W 0402; Alternate Manufacturer: Samsung Electro-Mechanics; Alternate Mfr Part #: RC1005F4122CS; MFG Part number: RC0402FR-0741K2L; Manufacturer: YAGEO; Part No.: RC0402FR-0741K2L
R12 = R: RES SMD 499K OHM 1% 1/16W 0402; MFG Part number: RC0402FR-07499KL; Manufacturer: YAGEO; Part No.: ERJ-1GEF4993C
R16 = R: RES SMD 200K OHM 1% 1/10W 0402; MFG Part number: ERJ-2RKF2003X; Manufacturer: PANASONIC ELECTRONIC COMPONENTS; Part No.: ERJ-1GEF2003C
R17 = R: RES SMD 10K OHM 1% 1/16W 0402; MFG Part number: RC1005F103CS; Manufacturer: Samsung Electro-Mechanics America, Inc
R18 = R: RES SMD 44.2K OHM 1% 1/16W 0402; MFG Part number: RC0402FR-0744K2L; Manufacturer: YAGEO; Part No.: ERJ-1GEF4422C
R60 = R: BOM_IG: NO LOAD; DNP: DNP; Part No.: ERJ-1GEF4322C
R61 = R: BOM_IG: NO LOAD; Part No.: ERJ-1GEF4322C
TP2 = TEST_POINT: TEST POINT PC MINI .040"D YELLOW; CLASS: DISCRETE; DIGI-KEY PART NO: 36-5004-ND; DNP: DNP; MFG Part number: 5004; Manufacturer: Keystone Electronics; Mfr_Name: Keystone Electronics; Mfr_Part_Number: 5000; PART_NUMBER: 5000; Package Type: TH; Part Number: 400-00001; Price: 0.36; Section: Power Supply
U1 = mp8759_0: IC SYNC BUCK CONVERTER 8A 26V; Manufacturer: MPS
U2 = MP2162: IC REG BUCK ADJ 2A SYNC QFN; MFG Part number: MP2162GQH; Manufacturer: MPS
C14 = CAP_NP: CAP CER 10UF 50V X7R 1210; DIGI-KEY PART NO: 490-6544-1-ND; MFG Part number: GRM32ER71H106KA12L; Manufacturer: Murata Electronics North America; Price: 0.73; VOLTAGE: 50V
C49 = CAP_NP: CAP CER 0.1UF 50V 10% JB 0603; DIGI-KEY PART NO: 445-11261-1-ND; MFG Part number: C1608JB1H104K080AA; Manufacturer: TDK Corporation; Price: 0.1; Tolerance: 10%; VOLTAGE: 50V
C27-C29 C31 C34 C70 = CAP_NP: CAP CER 0.1UF 10V 10% X7R 0402; DIGI-KEY PART NO: 445-4958-1-ND; MFG Part number: C1005X7R1A104K050BB; Manufacturer: TDK Corporation; Price: 0.1; Tolerance: 10%; VOLTAGE: 10V
C116 C118 = 0.01uF-50V-10%-X7R-0603: CAP CER 0.1UF 50V 10% X5R 0402; DIGI-KEY PART NO: 445-5942-1-ND; MFG Part number: C1005X5R1H104K050BB; Manufacturer: TDK Corporation; Price: 0.13; Voltage: 50V
C117 = 1.0uF-50V-10%-X5R-0603: CAP CER 1UF 50V 10% X5R 0603; DIGI-KEY PART NO: 445-7468-1-ND; MFG Part number: C1608X5R1H105K080AB; Manufacturer: TDK Corporation; Price: 0.18; Voltage: 50V
C119 C123 C124 = 220uF-50V-20%-ALUM-10.5x10.5: CAP ALUM 330UF 50V 20% SMD; DIGI-KEY PART NO: PCE5026CT-ND; MFG Part number: EEE-FT1H331AP; Manufacturer: Panasonic Electronic Components; Price: 1.42
C120 = 0.1uF-25V-10%-X7R-0603: CAP CER 0.1UF 25V 10% X7R 0603; DIGI-KEY PART NO: 490-1524-1-ND; MFG Part number: GRM188R71E104KA01D; Manufacturer: Murata Electronics North America; Price: 0.1
C121 = 0.022uF-50V-10%-X7R-0603: CAP CER 0.47UF 50V 10% X7R 0603; DIGI-KEY PART NO: 445-5952-1-ND; MFG Part number: C1608X7R1H474K080AC; Manufacturer: TDK Corporation; Price: 0.24; Voltage: 50V
C122 = 470pF-50V-5%-NPO-0603: CAP CER 8200PF 50V 10% X7R 0402; DIGI-KEY PART NO: 399-3075-1-ND; MFG Part number: C0402C822K5RACTU; Manufacturer: Kemet; Price: 0.27
C140 = 470pF-50V-10%-X7R-0603: DIGI-KEY PART NO: 490-1489-1-ND; MFG Part number: GRM188R71H471KA01D; Manufacturer: Murata Electronics North America; Price: 0.1
C141 = 270pF-50V-5%-NPO-0402: DIGI-KEY PART NO: 490-1294-1-ND; MFG Part number: GRM1555C1H271JA01D; Manufacturer: Murata Electronics North America; Price: 0.1
D4 = BZX84C18_SOT_0: DIODE SCHOTTKY 30V 5A SOD128; DIGI-KEY PART NO: 568-6519-1-ND; Manufacturer: NXP Semiconductors; Price: 0.48
D10 = BZX84C18_SOT_0: TVS DIODE 24VWM 50VC DO214AA; DIGI-KEY PART NO: 497-3140-1-ND; Manufacturer: STMicroelectronics; Price: 0.42
D19 = DIO_ZENER_MMSZ4702T1G: DIGI-KEY PART NO: MMSZ4702T1GOSCT-ND; Manufacturer: On Semiconductor; Price: 0.23
D20 = DIO_SHOTTKY_MBR0540T1G_SOD123: DIODE SCHOTTKY 40V 0.5A SOD123; DIGI-KEY PART NO: MBR0540T1GOSCT-ND; Manufacturer: On Semiconductor; Price: 0.36
D21 = DIO_SHOTTKY_MMSD701T1G_SOD123: DIGI-KEY PART NO: MMSD701T1GOSCT-ND; Manufacturer: On Semiconductor; Price: 0.39
J1 = CONN_JACK_PWR_2: CONN PWR JACK DC RIGHT ANGLE THROUGH HOLE; DIGI-KEY PART NO: 732-5930-ND; Manufacturer: Wurth electronics; Price: 1.04
J12 = TERMINAL_BLOCK: TERMINAL BLOCK 5MM VERT 2POS PCB; DIGI-KEY PART NO: ED2600-ND; Manufacturer: On Shore Technology Inc.; Price: 0.46
L3 = IND_10uH_DCR-0.0255_9A: FIXED IND 10UH 9A 25.5 MOHM SMD; DIGI-KEY PART NO: SRP1245A-100MCT-ND; MFG Part number: SRP1245A-100M; Manufacturer: Bourns Inc.; Price: 1.54
Q3 Q4 Q8 Q9 = 2N7002DW-7-F_0: MOSFET 2N-CH 60V 0.23A SOT-363; DIGI-KEY PART NO: 2N7002DW-FDICT-ND; Manufacturer: Diodes Incorporated; Price: 0.39
Q5 = XISTOR_2N3904_SOT23_0: TRANS NPN 40V 0.2A SOT23; DIGI-KEY PART NO: MMBT3904LT1GOSCT-ND; MFG Part number: MMBT3904LT1G; Manufacturer: On Semiconductor; Mfg1_PN: <Mfg1_PN>; Price: 0.12
Q6 = N-MOSFET_NTMFS5834NL_DFN5: MOSFET N-CH 40V 13A SO-8FL; DIGI-KEY PART NO: NTMFS5834NLT1G-ND; MFG Part number: NTMFS5834NLT1G; Manufacturer: On Semiconductor
Q7 = N-MOSFET_NTTFS5826NL_DFN9_1: MOSFET N-CH 60V 8A 8-WDFN; DIGI-KEY PART NO: NTTFS5826NLTAGOSCT-ND; MFG Part number: NTTFS5826NLTAG; Manufacturer: On Semiconductor; Price: 0.73
R23 = R: RES SMD 60.4 OHM 1% 1/16W 0402; DIGI-KEY PART NO: 311-60.4LRCT-ND; MFG Part number: RC0402FR-0760R4L; Manufacturer: Yageo; Price: 0.1; Tolerance: 1%
R24 = R: RES SMD 30 OHM 1% 1/16W 0402; DIGI-KEY PART NO: 311-30LRCT-ND; MFG Part number: RC0402FR-0730RL; Manufacturer: Yageo; Price: 0.1; Tolerance: 1%
R26 = RESISTOR: RES SMD 5.49K OHM 1% 1/16W 0402; DIGI-KEY PART NO: 311-5.49KLRCT-ND; MFG Part number: RC0402FR-075K49L; Manufacturer: Yageo; Price: 0.1; Tolerance: 1%
R27 = RESISTOR: RES SMD 2.67K OHM 1% 1/16W 0402; DIGI-KEY PART NO: 311-2.67KLRCT-ND; MFG Part number: RC0402FR-072K67L; Manufacturer: Yageo; Price: 0.1; Tolerance: 1%
R28 = RESISTOR: RES SMD 1.5K OHM 1% 1/10W 0402; DIGI-KEY PART NO: P1.50KLCT-ND; MFG Part number: ERJ-2RKF1501X; Manufacturer: Panasonic Electronic Components; Price: 0.1; Tolerance: 1%
R29 = RESISTOR: RES SMD 1.13K OHM 1% 1/16W 0402; DIGI-KEY PART NO: RMCF0402FT1K13CT-ND; MFG Part number: RMCF0402FT1K13 / RMCF0402FT1K13; Manufacturer: Stackpole Electronics Inc.; Price: 0.1; Tolerance: 1%
R30-R35 = RESISTOR: RES SMD 100K OHM 5% 1/10W 0402; DIGI-KEY PART NO: P100KJCT-ND; MFG Part number: ERJ-2GEJ104X; Manufacturer: Panasonic Electronic Components; Price: 0.1; Tolerance: 5%
R108 = 300-1_10W-5%-0603: RES SMD 300 OHM 5% 1/10W 0603; DIGI-KEY PART NO: P300GCT-ND; MFG Part number: ERJ-3GEYJ301V; Manufacturer: Panasonic Electronic Components; Price: 0.1
R109 R113 R125 R170 = 10.0K-1_16W-1%-0603: RES SMD 10K OHM 1% 1/10W 0603; DIGI-KEY PART NO: P10.0KHCT-ND; MFG Part number: ERJ-3EKF1002V; Manufacturer: Panasonic Electronic Components; Price: 0.1
R110 = 5.1-1_4W-5%-1206: RES SMD 5.1 OHM 5% 1/10W 0603; DIGI-KEY PART NO: 541-5.1GCT-ND; MFG Part number: CRCW06035R10JNEA; Manufacturer: Vishay Dale; Price: 0.1; Wattage: 1/10W
R111 R124 = 3.01K-1_10W-1%-0603: RES SMD 0.0OHM JUMPER 1/10W 0603; DIGI-KEY PART NO: P0.0GCT-ND; MFG Part number: ERJ-3GEY0R00V; Manufacturer: Panasonic Electronic Components; Price: 0.10
R112 = 14.3K-1_10W-1%-0603: RES SMD 14.3K OHM 1% 1/10W 0603; DIGI-KEY PART NO: P14.3KHCT-ND; MFG Part number: ERJ-3EKF1432V; Manufacturer: Panasonic Electronic Components; Price: 0.1
R115 = 150K-1_10W-1%-0603: 100k Ohm ±1% 0.1W, 1/10W Surface Mount Resistor Thick Film ±100ppm/°C 0603; DIGI-KEY PART NO: 311-100KHRCT-ND; MFG Part number: RC0603FR-07100KL; Manufacturer: Yageo; Price: 0.1
R118 = 21.0K-1_10W-1%-0603: RES SMD 10K OHM 1% 1/10W 0603; DIGI-KEY PART NO: P10.0KHCT-ND; MFG Part number: ERJ-3EKF1002V; Manufacturer: Panasonic Electronic Components; Price: 0.1
R123 = 16.9K-1_10W-1%-0603: RES SMD 16.9K OHM 1% 1/10W 0603; DIGI-KEY PART NO: P16.9KHCT-ND; MFG Part number: ERJ-3EKF1692V; Manufacturer: Panasonic Electronic Components; Price: 0.1
R127 = 619-1_10W-1%-0603: RES SMD 619 OHM 1% 1/10W 0603; DIGI-KEY PART NO: P619HCT-ND; MFG Part number: ERJ-3EKF6190V; Manufacturer: Panasonic Electronic Components; Price: 0.1
R129 R174 = 20.0K-1_10W-1%-0603: RES SMD 20K OHM 1% 1/10W 0603; DIGI-KEY PART NO: P20.0KHCT-ND; MFG Part number: ERJ-3EKF2002V; Manufacturer: Panasonic Electronic Components; Price: 0.1
R176 = 100-1_10W-1%-0603: RES SMD 100 OHM 1% 1/10W 0603; DIGI-KEY PART NO: P100HCT-ND; MFG Part number: ERJ-3EKF1000V; Manufacturer: Panasonic Electronic Components; Price: 0.1
R177 = 5.49K-1_10W-1%-0603: RES SMD 5.49K OHM 1% 1/10W 0603; DIGI-KEY PART NO: P5.49KHCT-ND; DNL: DNL; MFG Part number: ERJ-3EKF5491V; Manufacturer: Panasonic Electronic Components; Price: 0.1
R179 = 20-1_10W-5%-0603: RES SMD 20 OHM 5% 1/10W 0603; DIGI-KEY PART NO: P20GCT-ND; MFG Part number: ERJ-3GEYJ200V; Manufacturer: Panasonic Electronic Components; Price: 0.1
R182 = 3.01K-1_10W-1%-0603: RES SMD 1K OHM 1% 1/10W 0603; DIGI-KEY PART NO: P1.00KHCT-ND; MFG Part number: ERJ-3EKF1001V; Manufacturer: Panasonic Electronic Components; Price: 0.10
U3 = NCP1034_SOIC16: DIGI-KEY PART NO: NCP1034DR2GOSCT-ND; MFG Part number: NCP1034DR2G; Manufacturer: On Semiconductor; Price: 2.89
U4 = CD74HC238PWR: IC DECODER/DEMUX HS 3-8 16-TSSOP; DIGI-KEY PART NO: 296-13814-1-ND; Manufacturer: Texas Instruments; Price: 0.57
TYPE-C_VBUS TYPE-C_VBUS1 USB_C_PWR USB_P_PWR = TEST_POINT: TEST POINT PC MINI .040"D RED; DIGI-KEY PART NO: 36-5000-ND; MFG Part number: 5000; Manufacturer: Keystone Electronics; Price: 0.36
DP_PWR Vfb = T_POINT_R: TEST POINT PC MINI .040"D RED; DIGI-KEY PART NO: 36-5000-ND; DNL: DNL; MFG Part number: 5000; Manufacturer: Keystone Electronics; Price: 0.36
C143 = 10uF-50V-10%-X5R-1206: CAP CER 10UF 50V X7R 1210; DIGI-KEY PART NO: 490-6544-1-ND; MFG Part number: GRM32ER71H106KA12L; Manufacturer: Murata Electronics North America; Price: 0.1; Voltage: 50V
C144 C146 C161 = 10uF-50V-10%-X5R-1206: CAP CER 4.7UF 50V X7R 1210; DIGI-KEY PART NO: 490-10962-1-ND; MFG Part number: GRJ32ER71H475KE11L; Manufacturer: Murata Electronics North America; Price: 0.89; Voltage: 50V
C32 C40 C162 = CAP_NP: CAP CER 2200PF 2KV 10% X7R 1808; DIGI-KEY PART NO: 709-1306-1-ND; MFG Part number: 202R29W222KV4E; Manufacturer: Johanson Dielectrics Inc.; Price: 0.49; Tolerance: 10%; VOLTAGE: 2KV
D29 = BZX84C18_SOT_1: TVS DIODE 24VWM 38.9VC SMB; DIGI-KEY PART NO: SMBJ24CA-E3/52GICT-ND; Manufacturer: Vishay Semiconductor Diodes Division; Price: 0.41
D30-D35 = BZX84C18_SOT_1: TVS DIODE 5.5VWM 14VC TSLP2-2; DIGI-KEY PART NO: ESD105B102ELE6327XTMA1CT-ND; MFG Part number: ESD105B102ELE6327XTMA1; Manufacturer: Infineon Technologies; Price: 0.45
J18 = TERMINAL_BLOCK: TERM BLOCK PCB 2POS 5.0MM GREEN; DIGI-KEY PART NO: 277-1667-ND; Manufacturer: Phoenix Contact; Price: 0.37
J19 = USB-PD_TYPE-C_20: USB TYP C TP MNT DL RW SMT RECEP; DIGI-KEY PART NO: 670-2794-1-ND; Manufacturer: JAE Electronics; Price: 2.61
Q1 Q2 = MOSFET_N_GDS_10: MOSFET 2N-CH 30V 11A 8SOIC; DIGI-KEY PART NO: 785-1688-1-ND; Manufacturer: Alpha & Omega Semiconductor Inc.; Price: 0.67
R185 = RESISTOR: RES SMD 0.01 OHM 1% 2W 2512; DIGI-KEY PART NO: RHM.010AUCT-ND; MFG Part number: PMR100HZPFU10L0; Manufacturer: Rohm Semiconductor; Price: 0.77; TOLERANCE: 1%; WATT: 2W
R189 = 100-16W-1%-2512: RES SMD 200 OHM 1% 3W 2512; DIGI-KEY PART NO: A121182CT-ND; MFG Part number: 3522200RFT; Manufacturer: TE Connectivity AMP Connectors; Price: 0.83; Wattage: 3W
R192-R195 = R: RES SMD 10M OHM 5% 1/16W 0402; DIGI-KEY PART NO: RHM10MBICT-ND; MFG Part number: TRR01MZPJ106; Manufacturer: Rohm Semiconductor; Price: 0.11; Tolerance: 5%
R41 R47 R183 R219 = 10K-1_16W-5%-0603: RES SMD 100K OHM 5% 1/10W 0402; DIGI-KEY PART NO: P100KJCT-ND; MFG Part number: ERJ-2GEJ104X; Manufacturer: Panasonic Electronic Components; Price: 0.1
C25 C26 = Cap: CAP CER 10000PF 25V 10% X7R 0402; DIGI-KEY PART NO: 478-1113-1-ND; MFG Part number: 04023C103KAT2A; Manufacturer: AVX Corporation; Price: 0.29; Tolerance: 10%; VOLTAGE: 25V
C33 = CAP-NP_0: CAP CER 1UF 10V X5R 0402; DIGI-KEY PART NO: 490-3890-1-ND; MFG Part number: GRM155R61A105KE15D; Manufacturer: Murata Electronics North America; Price: 0.1; RATED_VOLTAGE: <RATED_VOLTAGE>; VOLTAGE: 10V
C35 = Cap: CAP CER 2.2UF 25V 10% X5R 0603; DIGI-KEY PART NO: 445-5964-1-ND; MFG Part number: C1608X5R1E225K080AB; Manufacturer: TDK Corporation; Price: 0.24; Tolerance: 10%; VOLTAGE: 25V
C36-C39 = CAP_NP: CAP CER 0.22UF 16V X7R 0402; DIGI-KEY PART NO: 311-1708-1-ND; MFG Part number: CC0402KRX7R7BB224; Manufacturer: Yageo; Price: 0.1; VOLTAGE: 16V
J2 = USB3_TYPE-B_3: Connector Receptacle USB TypeB 3.0, Super Speed 9 Position Through Hole, Right Angle, Horizontal; DIGI-KEY PART NO: GSB3211311WEU-ND; Manufacturer: Foxconn; Price: 2.39
J4 = DISPLAY_PORT_CONN_10: Connector Receptacle DisplayPort 20 Position Surface Mount, Right Angle, Horizontal; DIGI-KEY PART NO: WM19271CT-ND; MFG Part number: 472720001; Manufacturer: Molex, LLC; Price: 5.3
R36 R37 = R: RES SMD 2K OHM 5% 1/16W 0402; DIGI-KEY PART NO: 311-2.0KJRCT-ND; MFG Part number: RC0402JR-072KL; Manufacturer: Yageo; Price: 0.1; Tolerance: 5%
R38 R40 = R: RES SMD 4.7K OHM 5% 1/16W 0402; DIGI-KEY PART NO: 311-4.7KJRCT-ND; MFG Part number: RC0402JR-074K7L; Manufacturer: Yageo; Price: 0.1; Tolerance: 5%
R42-R45 R48-R50 R52 = R: RES SMD 4.7K OHM 5% 1/16W 0402; DIGI-KEY PART NO: 311-4.7KJRCT-ND; DNL: DNL; MFG Part number: RC0402JR-074K7L; Manufacturer: Yageo; Price: 0.1; Tolerance: 5%
R46 R51 = RESISTOR: RES SMD 1M OHM 1% 1/10W 0603; DIGI-KEY PART NO: 311-1.00MHRCT-ND; MFG Part number: RC0603FR-071ML; Manufacturer: Yageo; Price: 0.1; Tolerance: 1%
R53 = R_0: RES SMD 4.99K OHM 1% 1/10W 0402; DIGI-KEY PART NO: P4.99KLCT-ND; MFG Part number: ERJ-2RKF4991X; Manufacturer: Panasonic Electronic Components; Price: 0.1; Tolerance: 1%
R74 = RESISTOR: RES 10K OHM 1/16W 1% 0402; DIGI-KEY PART NO: 1276-3431-1-ND; MFG Part number: RC1005F103CS; Manufacturer: Samsung Electro-Mechanics America, Inc; Price: 0.1; Tolerance: 1%
U5 = IC-PS8122PinCTL_27: USB Type-C Redriving Switch for USB Host / DisplayPort Source; Manufacturer: Parade Technologies Ltd

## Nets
5V: C9.1 C10.1 R5.1 R12.1 R14.1 U2.7(VIN)
DGND: C14.2 C17.1 C18.2 C19.2 C20.1 C22.2 C23.2 C24.2 C25.2 C26.2 C27.1 C28.1 C29.1 C32.1 C33.1 C35.2 C40.1 C49.2 C61.2 C70.1 C116.2 C117.2 C119.2 C120.2 C122.2 C123.2 C124.2 C143.2 C144.2 C146.2 C148.2 C149.1 C150.2 C151.1 C152.1 C153.1 C154.1 C155.2 C159.2 C160.1 C161.1 C162.2 D10.A(ANODE) D19.A(ANODE) D24.A(ANODE) D26.A(ANODE) J1.2 J1.3 J2.4(GND) J2.7(GND_DRAIN) J4.2(GND_1) J4.5(GND_2) J4.8(GND_3) J4.11(GND_4) J4.16(GND_5) J4.19(RETURN) J12.2 J16.2 J18.2 J19.A1(GND_1) J19.A12(GND_2) J19.B1(GND_3) J19.B12(GND_4) LED2.2(CATHODE) Q3.1(S2) Q4.1(S2) Q7.1(S1) Q7.2(S2) Q7.3(S3) Q8.4(S1) Q9.4(S1) R20.1 R30.2 R31.2 R32.2 R33.2 R34.2 R35.2 R46.1 R47.2 R48.2 R49.2 R50.2 R51.1 R52.2 R53.2 R112.2 R113.2 R118.2 R125.2 R127.2 R129.2 R176.2 R177.2 R183.2 R196.1 R219.2 SW2.1 U3.6(PGND) U3.14(GND) U4.3(A2) U4.4(\\~{E}1) U4.5(\\~{E}2) U4.8(GND) U5.41(EPAD) U15.33(VSS) U15.EPAD U16.2(GND)
GND: C2.2 C3.2 C4.2 C5.1 C6.1 C8.2 C9.2 C10.2 C11.2 C12.2 C142.2 D3.A(ANODE) LED1.2(CATHODE) R7.2 R10.2 R15.2 R17.2 R18.2 R61.2 U1.2(PGND) U1.10(AGND) U2.3(AGND) U2.5(PGND)
GND_EARTH: C162.1 D29.A(ANODE) D30.A(ANODE) D31.A(ANODE) D32.A(ANODE) D33.A(ANODE) D34.A(ANODE) D35.A(ANODE) J19.SH_1(SH1) J19.SH_2(SH2) J19.SH_3(SH3) J19.SH_4(SH4) J19.SH_5(SH5) J19.SH_6(SH6) R219.1
V3P3: C12.1 C25.1 C26.1 C27.2 C28.2 C29.2 C142.1 J13.1 R13.1 R36.1 R37.1 R38.2 R40.2 R41.1 R42.1 R43.1 R44.1 R45.1 R74.1 TP3.1 U5.6(VDD33_1) U5.20(VDD33_3) U5.28(VDD33_2)
V5P0: C19.1 C70.2 J13.3 R1.2 R2.1 R5.2 TP1.1 U4.6(E3) U4.16(VCC) U16.1(EN) U16.4(VIN)
V24P0: D5.A(ANODE) R15.1
VBUS_C_CTRL0: R201.1 U15.30(VBUS_C_CTRL0)
VBUS_C_CTRL1: R204.1 U15.29(VBUS_C_CTRL1)
VBUS_DISCHRG: R189.2 U15.32(VBUS_DISCHARGE)
VBUS_P_CTRL0: R197.1 U15.2(VBUS_P_CTRL0)
VBUS_P_CTRL1: R200.1 U15.1(VBUS_P_CTRL1)
VDDD: C150.1 C151.2 J14.3 U15.17(VDDD)
VDDIO: C24.1 C152.2 J14.2 R205.1 R209.1 R211.1 U15.18(VDDIO)
24DC: C14.1 C49.1 C61.1 C124.1 D4.C(CATHODE) D10.C(CATHODE) Q6.5(D1) R108.1 R109.1 R115.1
24DCIN: D4.A(ANODE) J1.1 J12.1
ADDR1: R42.2 R48.1 U5.14(ADDR1/DPEQ)
AUX_N: J4.17(AUX_CH_N) R41.2 U5.25(AUXn)
AUX_P: J4.15(AUX_CH_P) R47.1 U5.24(AUXp)
CC1: C20.2 D32.C(CATHODE) J19.A5(CC1) U15.5(CC1)
CC2: C17.2 D33.C(CATHODE) J19.B5(CC2) U15.3(CC2)
CDE: R44.2 R50.1 U5.35(CDE)
CEQ: R43.2 R49.1 U5.38(CEQ)
DC_PWR: C8.1 C11.1 D3.C(CATHODE) DC_PWR.1 R9.1 R19.1 U1.1(VIN)
DP_AUXN: R79.2 U5.27(SBU1) U15.14(P1.7/AUX_N)
DP_AUXP: R80.2 U5.26(SBU2) U15.11(P1.6/AUX_P)
En_3V3: R14.2 U2.1(EN)
HOTPLUG_DET: R77.2 U15.35(P3.3)
I2C_ADDR: U5.11(ADDR0/SSEQ)
I2C_SCL: R37.2 U5.21(CSCL/SW0) U15.9(P1.2)
I2C_SDA: R36.2 U5.22(CSDA/SW1) U15.10(P1.3)
ML0N: J4.10(ML_LANE_0N) U5.10(ML0n)
ML0P: J4.12(ML_LANE_0P) U5.9(ML0p)
ML1N: J4.7(ML_LANE_1N) U5.13(ML1n)
ML1P: J4.9(ML_LANE_1P) U5.12(ML1p)
ML2N: J4.4(ML_LANE_2N) U5.16(ML2n)
ML2P: J4.6(ML_LANE_2P) U5.15(ML2p)
ML3N: J4.1(ML_LANE_3N) U5.19(ML3n)
ML3P: J4.3(ML_LANE_3P) U5.18(ML3p)
MOS_TYPE_GPIOP2_4: U15.23(P2.4)
PG_3V3: R12.2 U2.8(PG)
PG_5V: R3.1 R60.1 TP2.1
SBU1: D30.C(CATHODE) J19.A8(SBU1) R79.1 U15.12(P1.4/SBU1)
SBU2: D31.C(CATHODE) J19.B8(SBU2) R80.1 U15.13(P1.5/SBU2)
SEL1: Q3.2(G2) R32.1 U4.15(Y0)
SEL2: Q8.5(G1) R33.1 U4.14(Y1)
SEL3: Q4.2(G2) R34.1 U4.13(Y2)
SEL4: Q9.5(G1) R35.1 U4.12(Y3)
SH_GND: C40.2 J4.21(SH1) J4.22(SH2) J4.23(SH3) J4.24(SH4)
SH_USB_B: C32.2 J2.19(SH1) J2.20(SH2) R183.1
SS_RXN: J2.8(STDB_SSRX-) U5.7(SSTXn)
SS_RXP: J2.9(STDB_SSRX+) U5.8(SSTXp)
SS_TXN: C34.2 U5.4(SSRXn)
SS_TXN_C: C34.1 J2.5(STDB_SSTX-)
SS_TXP: C31.2 U5.5(SSRXp)
SS_TXP_C: C31.1 J2.6(STDB_SSTX+)
SSDE: R45.2 R52.1 U5.3(SSDE)
SW2: R39.1
SWD0_CLK_GPIOP2_1: R215.1 U15.16(P2.1/SWD_CLK)
SWD0_DAT_GPIOP2_0: R216.1 U15.15(P2.0/SWD_IO)
SWD_CLK: J16.4 R215.2
SWD_IO: J16.5 R216.2
TX1N: C37.1 U5.34(TX1n)
TX1P: C36.1 U5.33(TX1p)
TX2N: C39.1 U5.36(TX2n)
TX2P: C38.1 U5.37(TX2p)
TYPE-C_VBUS: C15.2 C144.1 C159.1 C160.2 C161.2 D26.C(CATHODE) D29.C(CATHODE) J19.A4(VBUS_1) J19.A9(VBUS_2) J19.B4(VBUS_3) J19.B9(VBUS_4) Q1.7(D2) Q1.8(D2) Q2.5(D1) Q2.6(D1) R189.1 TYPE-C_VBUS.1 TYPE-C_VBUS1.1 U15.31(VBUS)
USB2_DM: U15.22(D-)
USB2_DP: U15.21(D+)
USB3_D+: D34.C(CATHODE) J2.3(D+) J19.A6(D+) J19.B6(D+)
USB3_D-: D35.C(CATHODE) J2.2(D-) J19.B7(D-)
USB3_VBUS: C33.2 J2.1(VBUS)
USB_C_PWR: C146.1 D22.A(ANODE) J18.1 Q2.7(D2) Q2.8(D2) R17.1 USB_C_PWR.1
USB_P_PWR: C119.1 C123.1 D24.C(CATHODE) L3.2 R179.1 R185.1 U15.40(CSP/VBUS_P) USB_P_PWR.1
USB_P_PWR_SENSE: C143.1 C145.2 Q1.5(D1) Q1.6(D1) R185.2 U15.39(CSN)
USB_PD_C_RX1+: J19.B11(RX1+) U5.30(RX1p)
USB_PD_C_RX1-: J19.B10(RX1-) U5.31(RX1n)
USB_PD_C_RX2+: J19.A11(RX2+) U5.40(RX2p)
USB_PD_C_RX2-: J19.A10(RX2-) U5.39(RX2n)
USB_PD_C_TX1+: C36.2 J19.A2(TX1+)
USB_PD_C_TX1-: C37.2 J19.A3(TX1-)
USB_PD_C_TX2+: C38.2 J19.B2(TX2+)
USB_PD_C_TX2-: C39.2 J19.B3(TX2-)
Vfb: R22.1 R23.1 R24.1 R25.1 R123.2 R177.1 R182.2 U3.2(FB) Vfb.1(TP)
VSEL1: R30.1 U4.1(A0) U15.28(P0.1)
VSEL2: R31.1 U4.2(A1) U15.27(P0.0)
VSYS: C22.1 C154.2 J13.2 J14.1 R208.2 R209.2 U15.20(VSYS)
VTARG: J16.1
XRES: J16.3 R214.2
XRES_PMG1-S2: C155.1 R211.2 R214.1 SW2.2 U15.26(XRES)
N03209: D19.K(CATHODE) Q5.1(BASE) R109.2
N03351: C116.1 C117.1 D21.A Q5.2(EMITTER) U3.8(DRVCC) U3.12(VCC)
N03467: D21.K R111.1 U3.9(VB)
N03479: C118.1 R111.2
N03483: C118.2 C140.1 L3.1 R170.2 R174.2
N03503: R113.1 R115.2 U3.16(UVLO)
N03591: D20.K R110.1 U3.10(HDRV)
N03595: D20.A Q6.4(G) R110.2 R174.1
N03781: R125.1 U3.5(SYNC)
N03817: Q6.1(S1) Q6.2(S2) Q6.3(S3)
N03881: R112.1 U3.15(RT)
N03889: R170.1 U3.13(OCin)
N03945: C120.1 U3.4(SS/~{SD})
N03953: R124.1 U3.7(LDRV)
N04107: R118.1 U3.1(OCset)
N04119: C140.2 R176.1
N04123: C141.1 R123.1 R179.2
N04185: Q7.6(D2) Q7.7(D3) Q7.8(D4) Q7.9(D_PAD)
N04217: C121.1 C122.1 U3.3(COMP)
N04315: Q7.4(G) R124.2 R129.1
N04495: C121.2 R127.1
N05161: Q3.6(D2) R26.1
N05165: Q8.3(D1) R27.1
N05169: Q4.6(D2) R28.1
N05173: Q9.3(D1) R29.1
N64491: D5.C(CATHODE) D22.C(CATHODE) R19.2
N64821: C2.1 U1.9(VCC)
N64879: C1.2 L1.1 R6.1 U1.7(SW)
N64891: C3.1 C4.1 C5.2 C6.2 C7.2 L1.2 R2.2 R11.1 U1.5(OUT)
N65085: C7.1 R6.2 R8.2
N65153: R9.2 R10.1 U1.12(EN)
N65255: R3.2 U1.3(PG)
N65267: R7.1 R8.1 R11.2 U1.11(FB)
N65271: R60.2 R61.1 U1.6(MODE)
N142229: L2.1 U2.6(SW)
N142233: C13.1 L2.2 R13.2 R16.1 U2.4(OUT)
N142459: C13.2 R16.2 R18.1 U2.2(FB)
N145404: C35.1 U5.1(CEXT)
N146086: R39.2 U5.23(SW2)
N146562: R74.2 R184.1 U5.32(IN_HPD)
N146972: J4.18(HotPlugDetect) R77.1 R184.2
N147016: R40.1 U5.29(EN)
N147716: R53.1 U5.2(REXT)
N149559: Q1.1(S2) Q1.3(S1) S1.1(TP)
N149567: Q2.1(S2) Q2.3(S1) S2.1(TP)
N150039: C145.1 Q1.4(G1) R192.2 R197.2
N150043: C15.1 Q2.4(G1) R194.2 R201.2
N150081: Q1.2(G2) R193.1 R200.2
N150119: Q2.2(G2) R195.1 R204.2
N150295: R20.2 R192.1 R193.2
N150343: R194.1 R195.2 R196.2
N152245: C18.1 C148.1 C149.2 U15.4(VCONN_SOURCE) U16.5(VOUT)
N152387: R205.2 R213.2 S3.1(TP) U16.3(FLAG)
N158053: C23.1 C153.2 U15.19(VCCD)
N168190: R213.1 U15.38(P3.6)
N270710: R38.1 U5.17(I2C_EN)
N270711: J4.14(CONFIG2) R51.2
N270716: J4.13(CONFIG1) R46.2
N270717: DP_PWR.1(TP) J4.20(DP_PWR)
N271570: R4.1 U1.8(BST)
N271571: C1.1 R4.2
N271574: LED1.1(ANODE) R1.1
N272445: R25.2 R29.2
N272446: R22.2 R26.2
N272447: R23.2 R27.2
N272448: Q5.3(COLLECTOR) R108.2
N272450: C141.2 R182.1
N272451: R24.2 R28.2
N279357: LED2.1(ANODE) R208.1

Not connected (* = marked no-connect by the designer): J19 A7(D-); Q7 5(D1); U1 4(NC)*; U3 11(VS); U4 7(Y7)* 9(Y6)* 10(Y5)* 11(Y4)*; U15 6(NC)* 7(P1.0)* 8(P1.1)* 24(P2.5)* 25(P2.6)* 34(P3.2)* 36(P3.4)* 37(P3.5)*

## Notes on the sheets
sheet 1
- PMG1-S2 CONTROLLER
- VCONN POWER SWITCH
- RESET
- J13 - VSYS SELECT
  1-2 short 3.3V (default)
  2-3 short 5V
- PMG1-S2 POWER ON
- PROGRAMMER
- J14 - IO SUPPLY SELECT
  1-2 short VSYS
  2-3 short VDDD (default)
sheet 2
- USB SUPERSPEED AND DISPLAY PORT MUX (OPTIONAL)
- Place 2.2uF
  close to CEXT
- Place Decaps
  close to VDD33/VDD
- Use mulitple vias connected to ground plane
  if the ground is not on the same layer as CEXT.
- USB 3 Type-B
- USB Type-C
  Re-driving Switch
- DISPLAY PORT
sheet 3
- STEP DOWN REGULATORS
- 1500mA
- Step-Down Regulator - 3.3V/1.5A
sheet 4
- PD REGULATOR
- 24VDC, 5A
- 5-20V DC, 5A POWER SUPPLY
- COLOUR: BLUE
- 2 : 4 DECODER
- IC REG LDO 5V
sheet 5
- PMG1-S2 DRP REFERENCE DESIGN
- CONTENTS
- PAGE
- DESCRIPTION
- 01
- TITLE & TABLE OF CONTENTS
- 02
- PMG1-S2 CONTROLLER
- 03
- STEP DOWN REGULATORS
- 04
- PD REGULATOR
- 05
- VBUS PROVIDER/CONSUMER FET AND TYPE-C CONNCETOR
- 06
- USB SUPERSPEED AND DISPLAY PORT MUX (Optional)
sheet 6
- VBUS PROVIDER/CONSUMER FET AND TYPE-C CONNECTOR
- Ensure layout is suitable for 5A continuous current for below path
  USB_P_PWR, TYPE-C_VBUS, USB_C_PWR
- OVER CURRENT SENSE
- PROVIDER PATH
- CONSUMER PATH
- USB Type-C
- CONSUMER POWER OUTPUT
  5 - 20V DC
- NOTE:
  Nets with names
  SS*, ML*, TX*, USB_PD*
  are all high speed signals
- COLOUR: GREEN
